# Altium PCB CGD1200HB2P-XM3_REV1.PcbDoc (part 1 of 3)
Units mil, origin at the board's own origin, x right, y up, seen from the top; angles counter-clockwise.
Board outline 2086.61 x 3149.61 mil, 6 copper layers (TOP, LAYER2, LAYER3, LAYER4, LAYER5, BOTTOM), stack 57.2 mil thick; 178 components, 101 nets, 513 pads, 419 vias.
Unrouted connection lines stored in the file: 206.
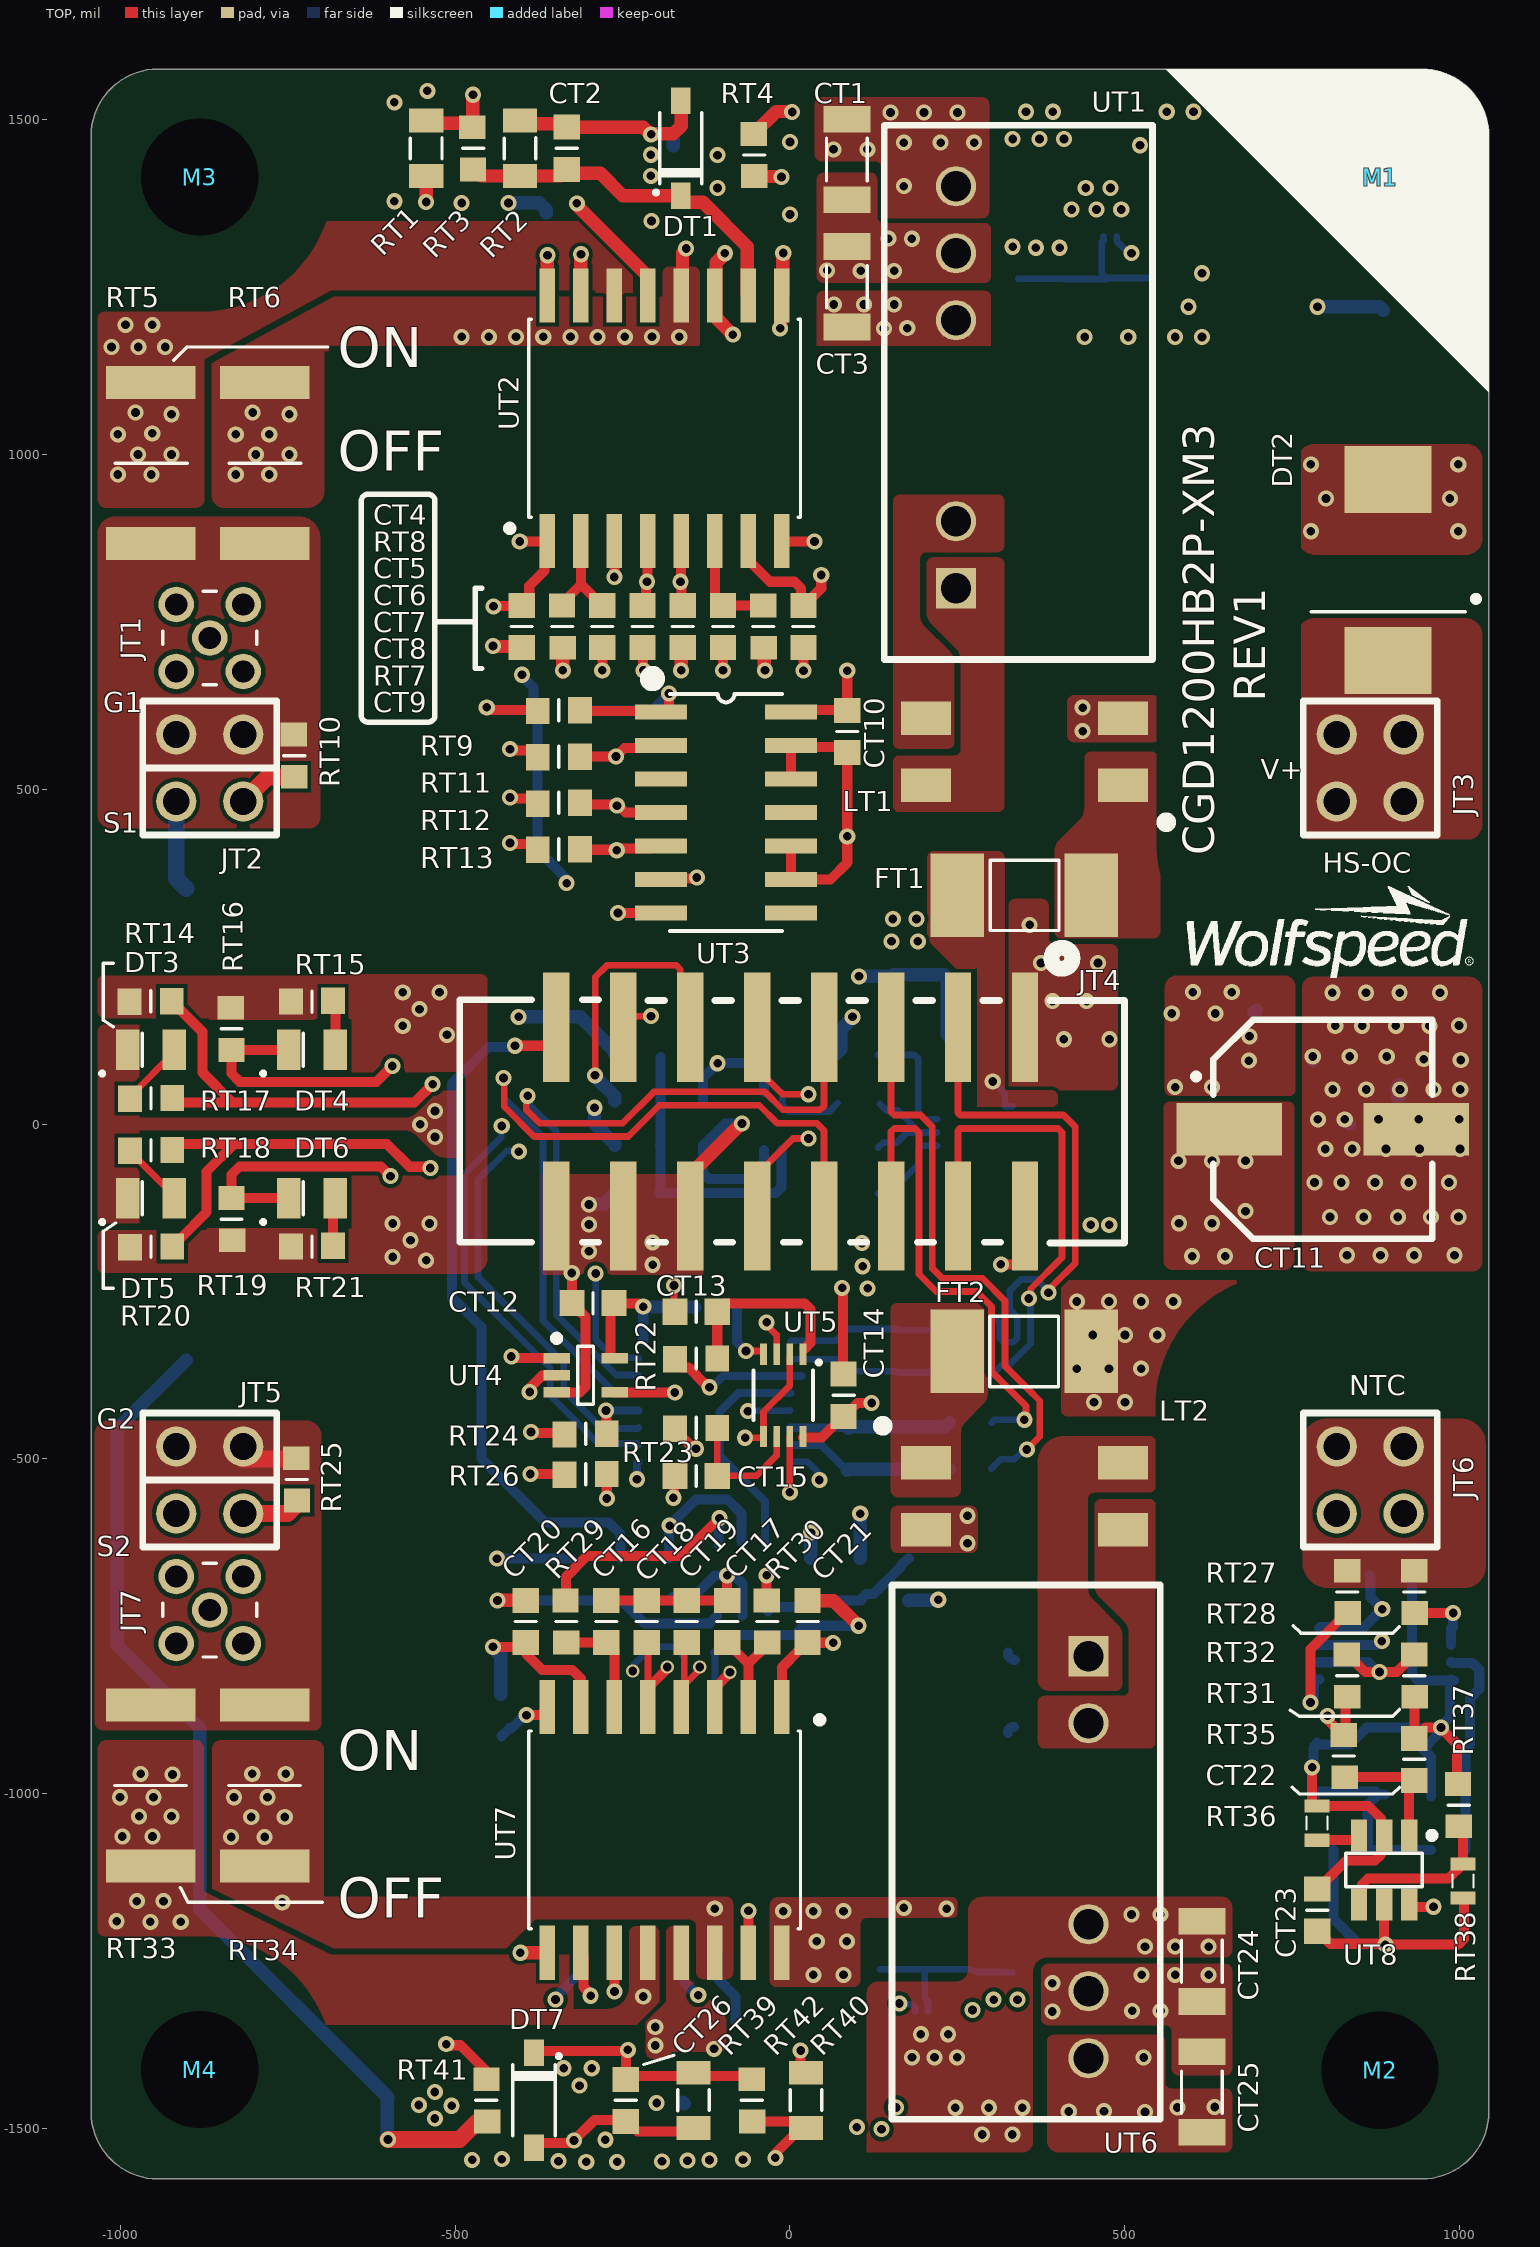
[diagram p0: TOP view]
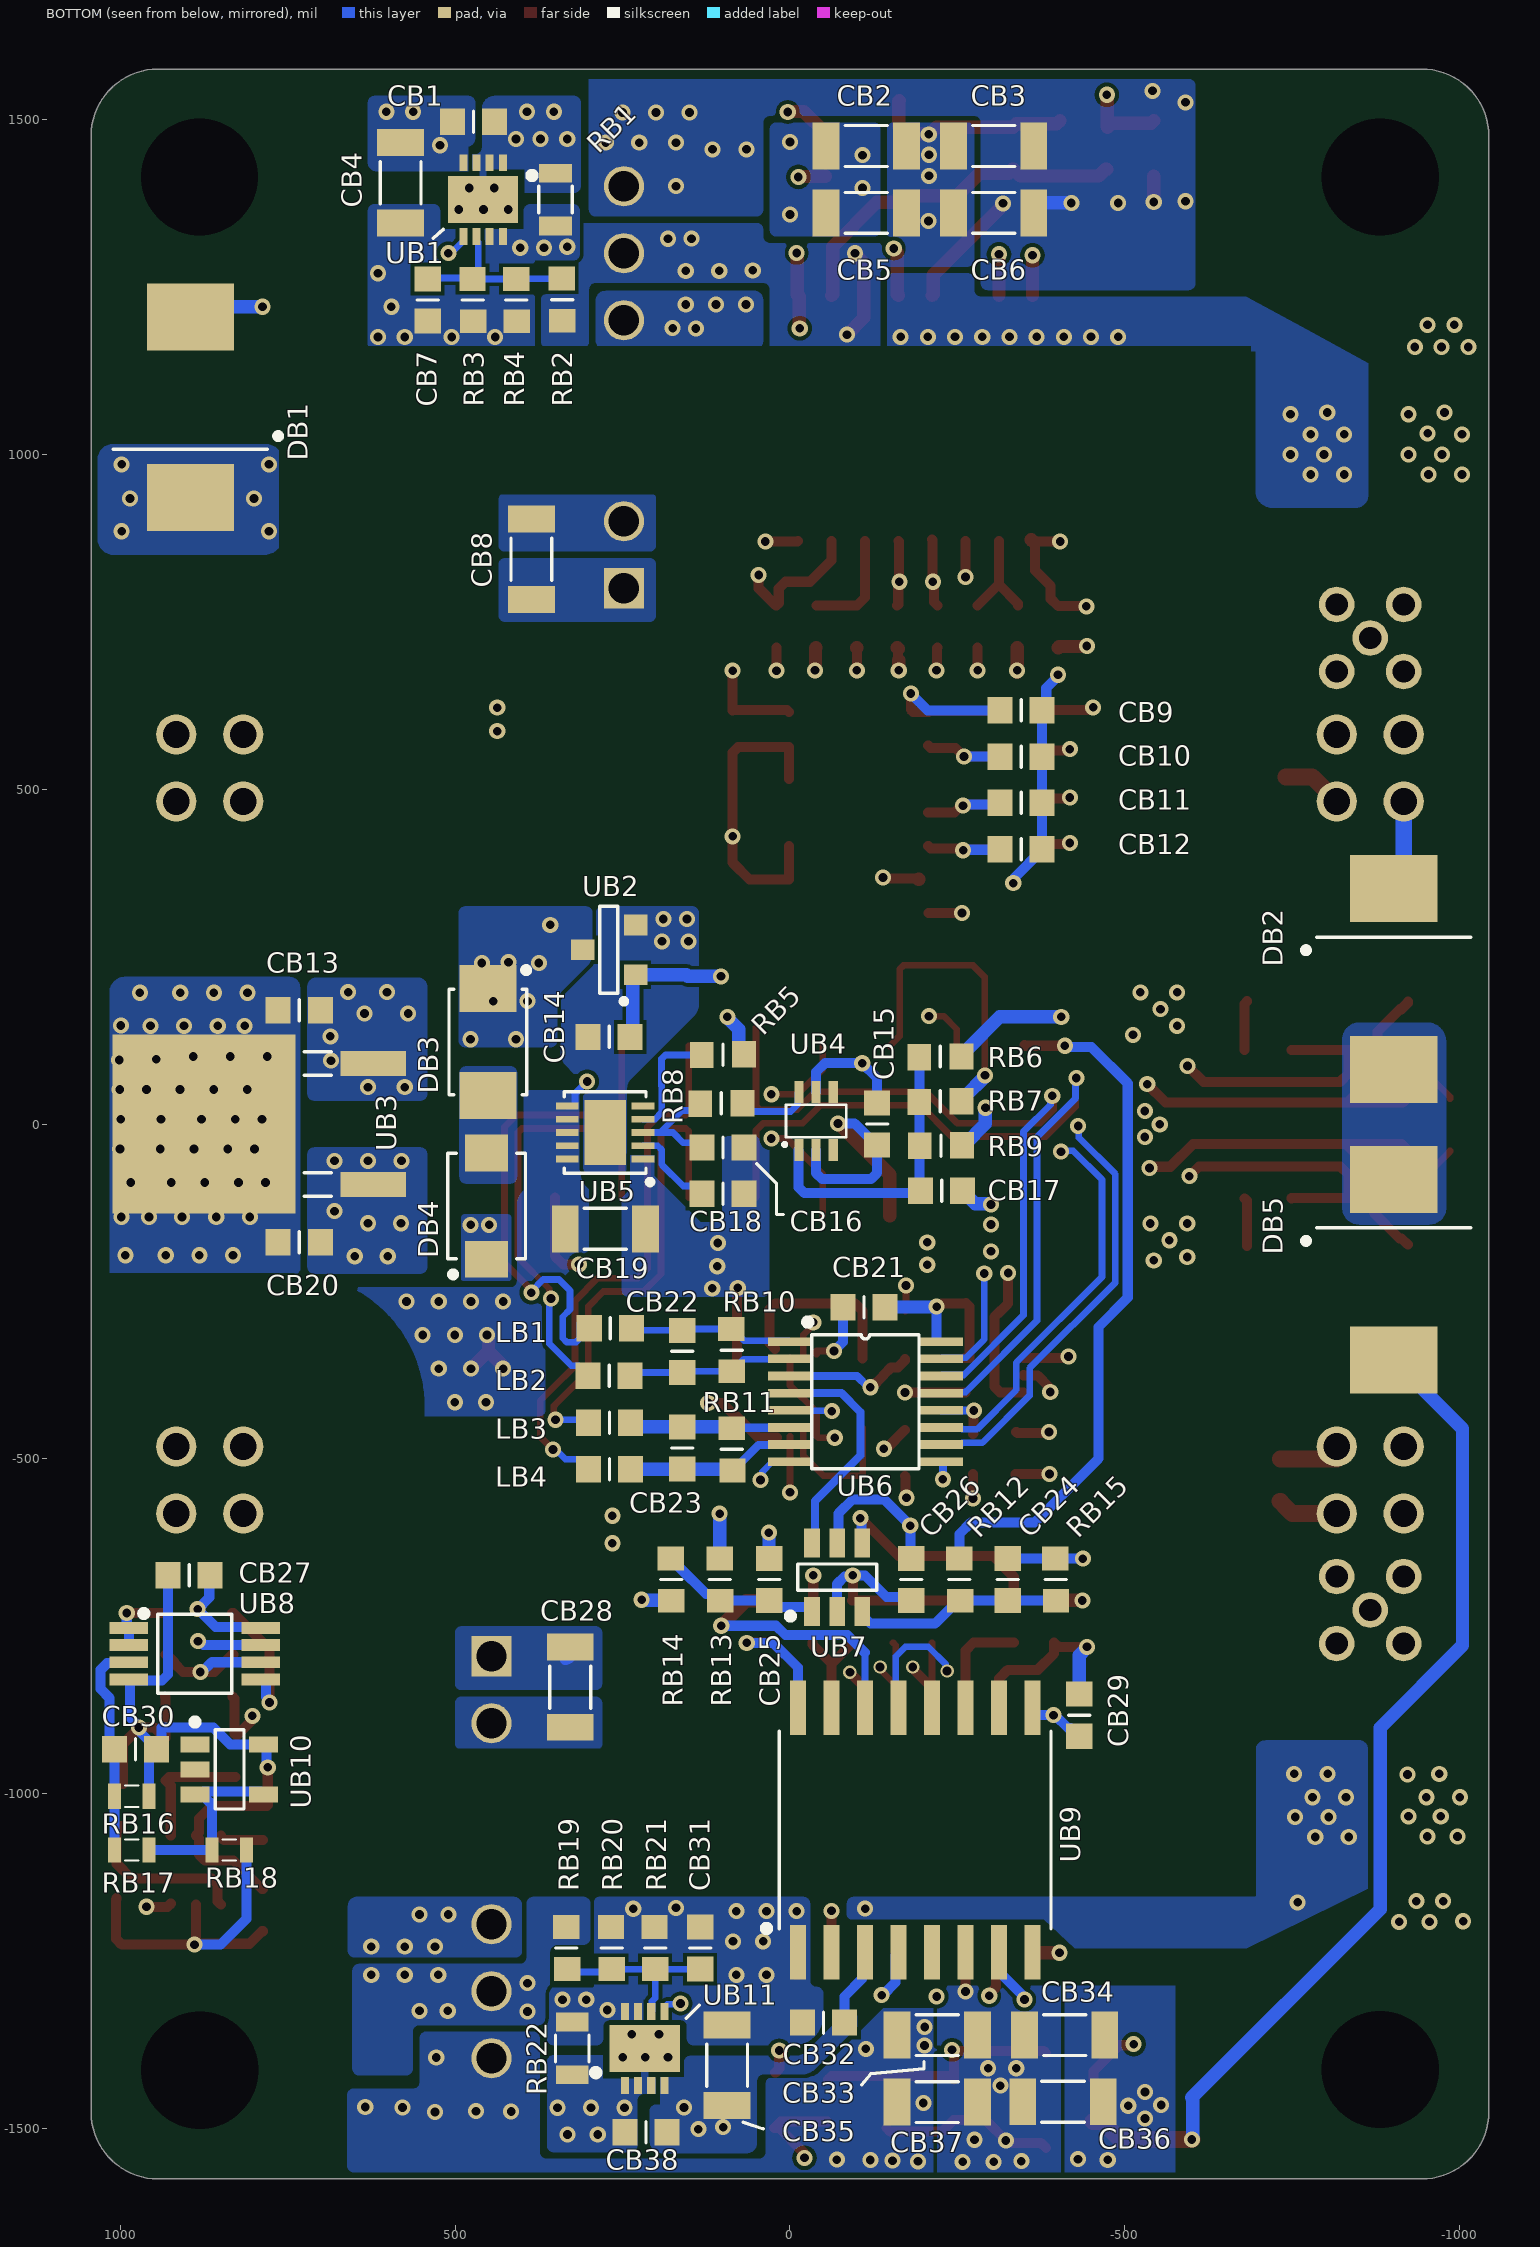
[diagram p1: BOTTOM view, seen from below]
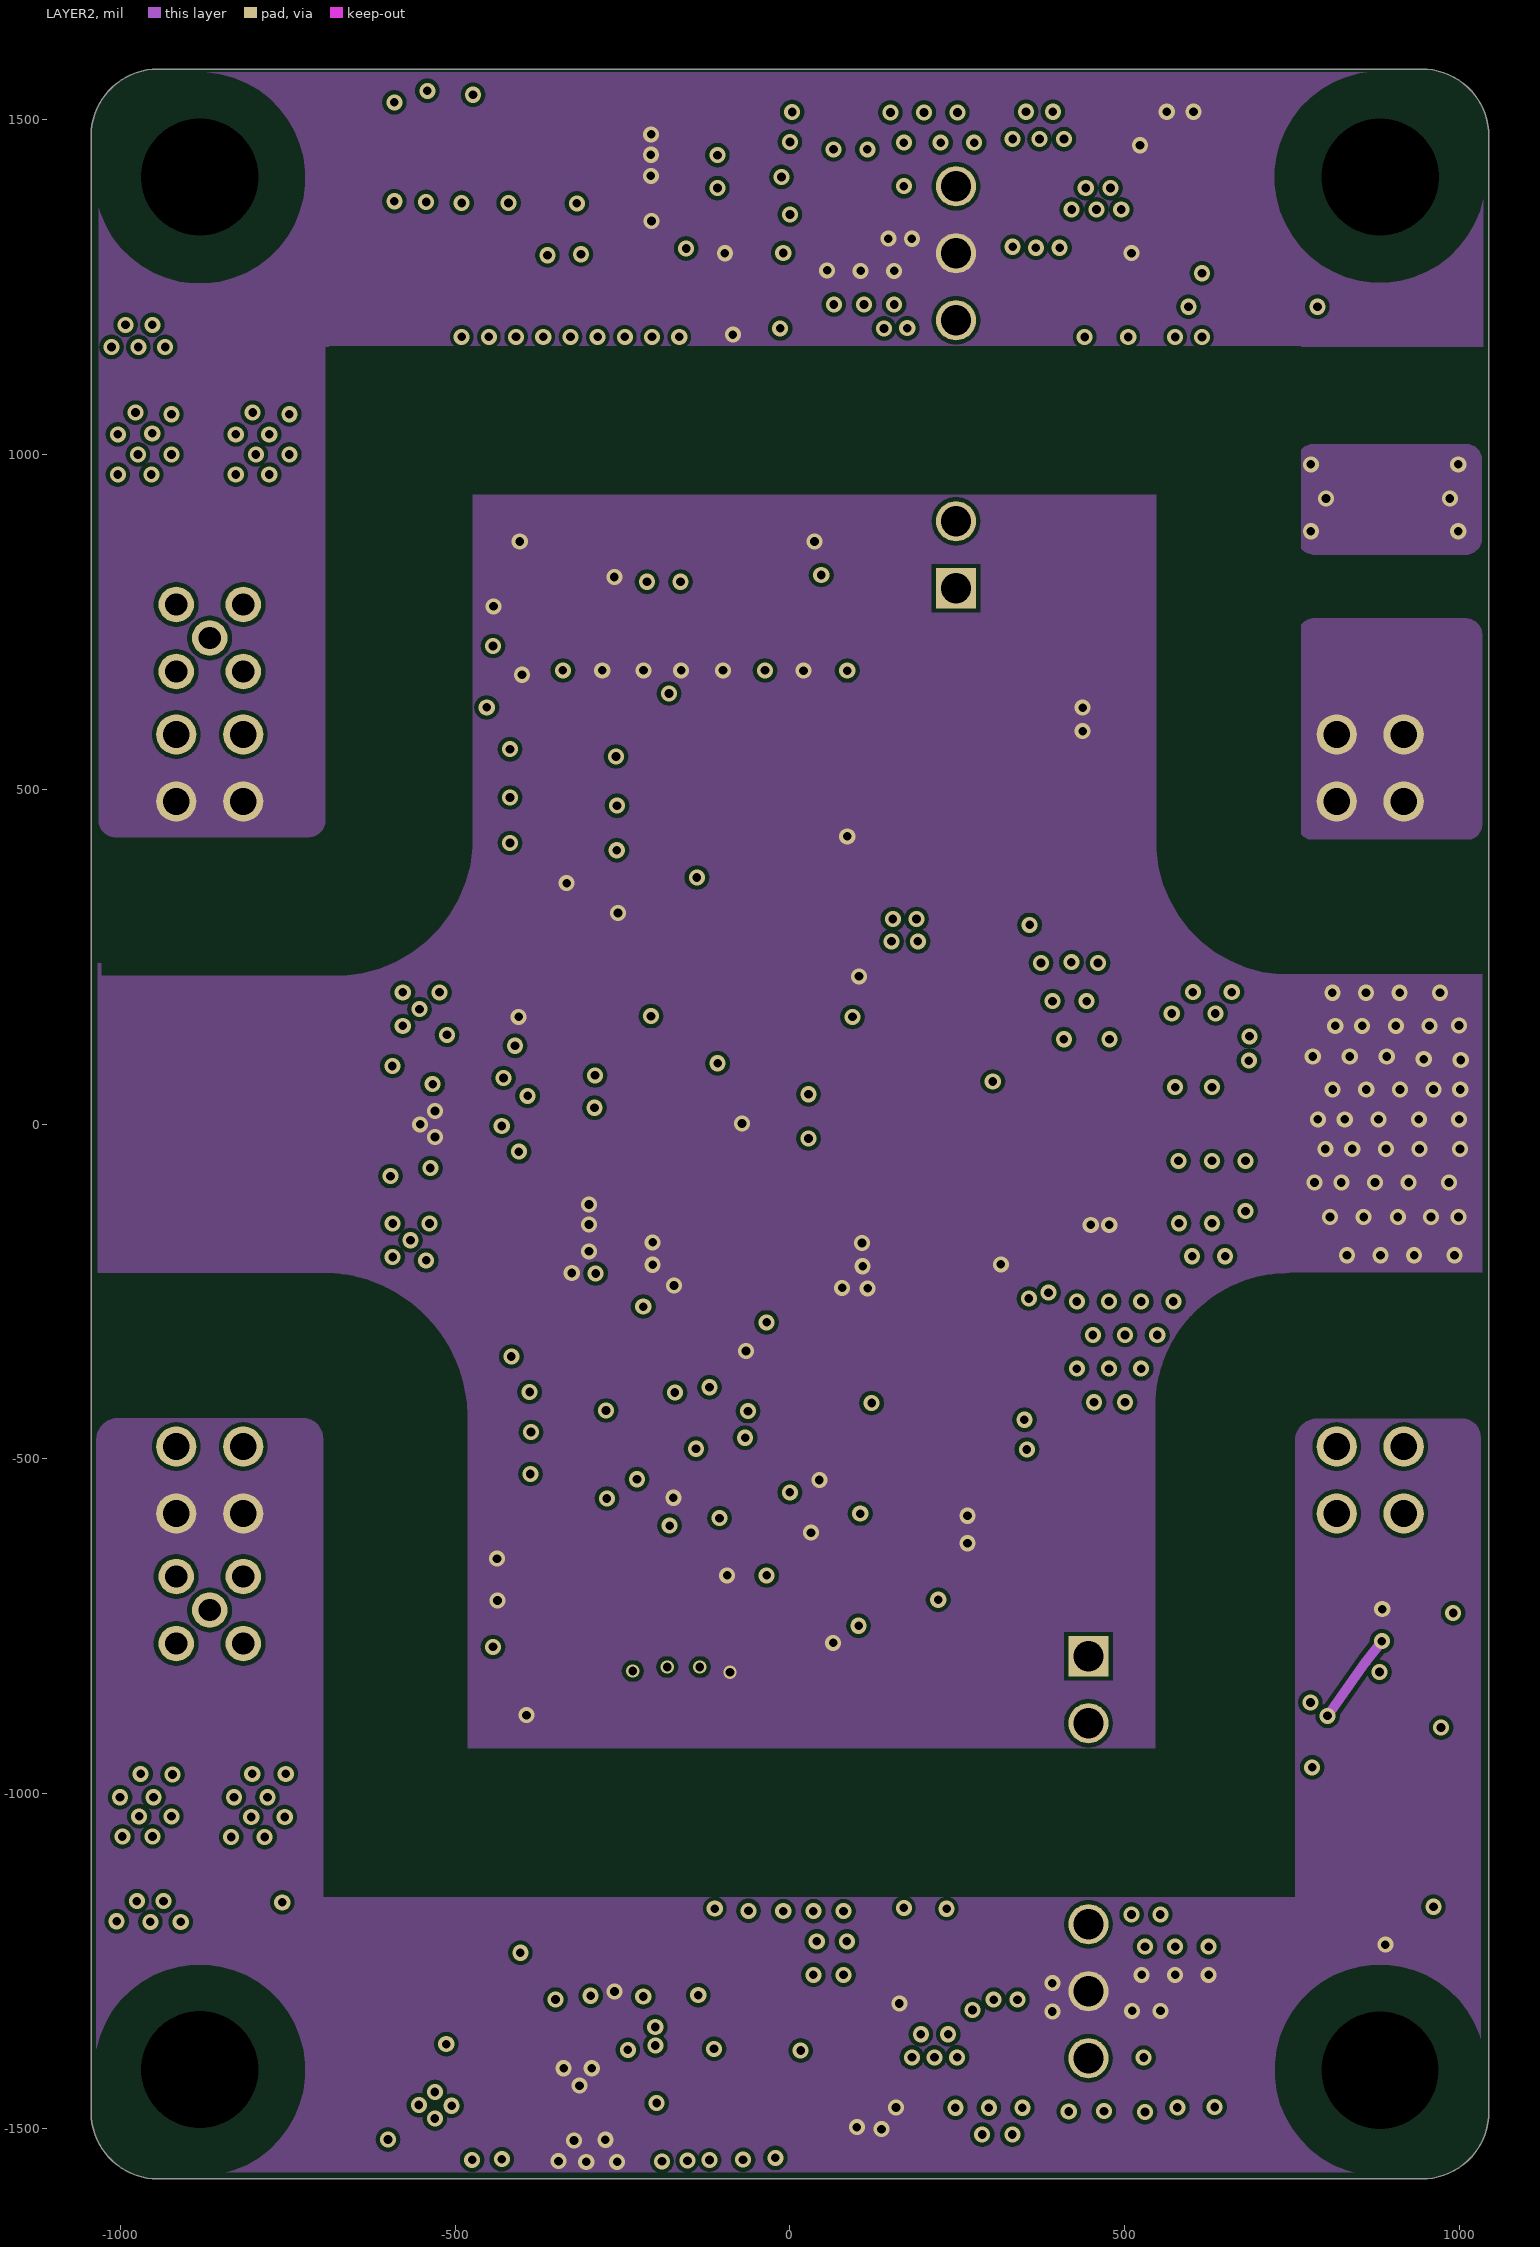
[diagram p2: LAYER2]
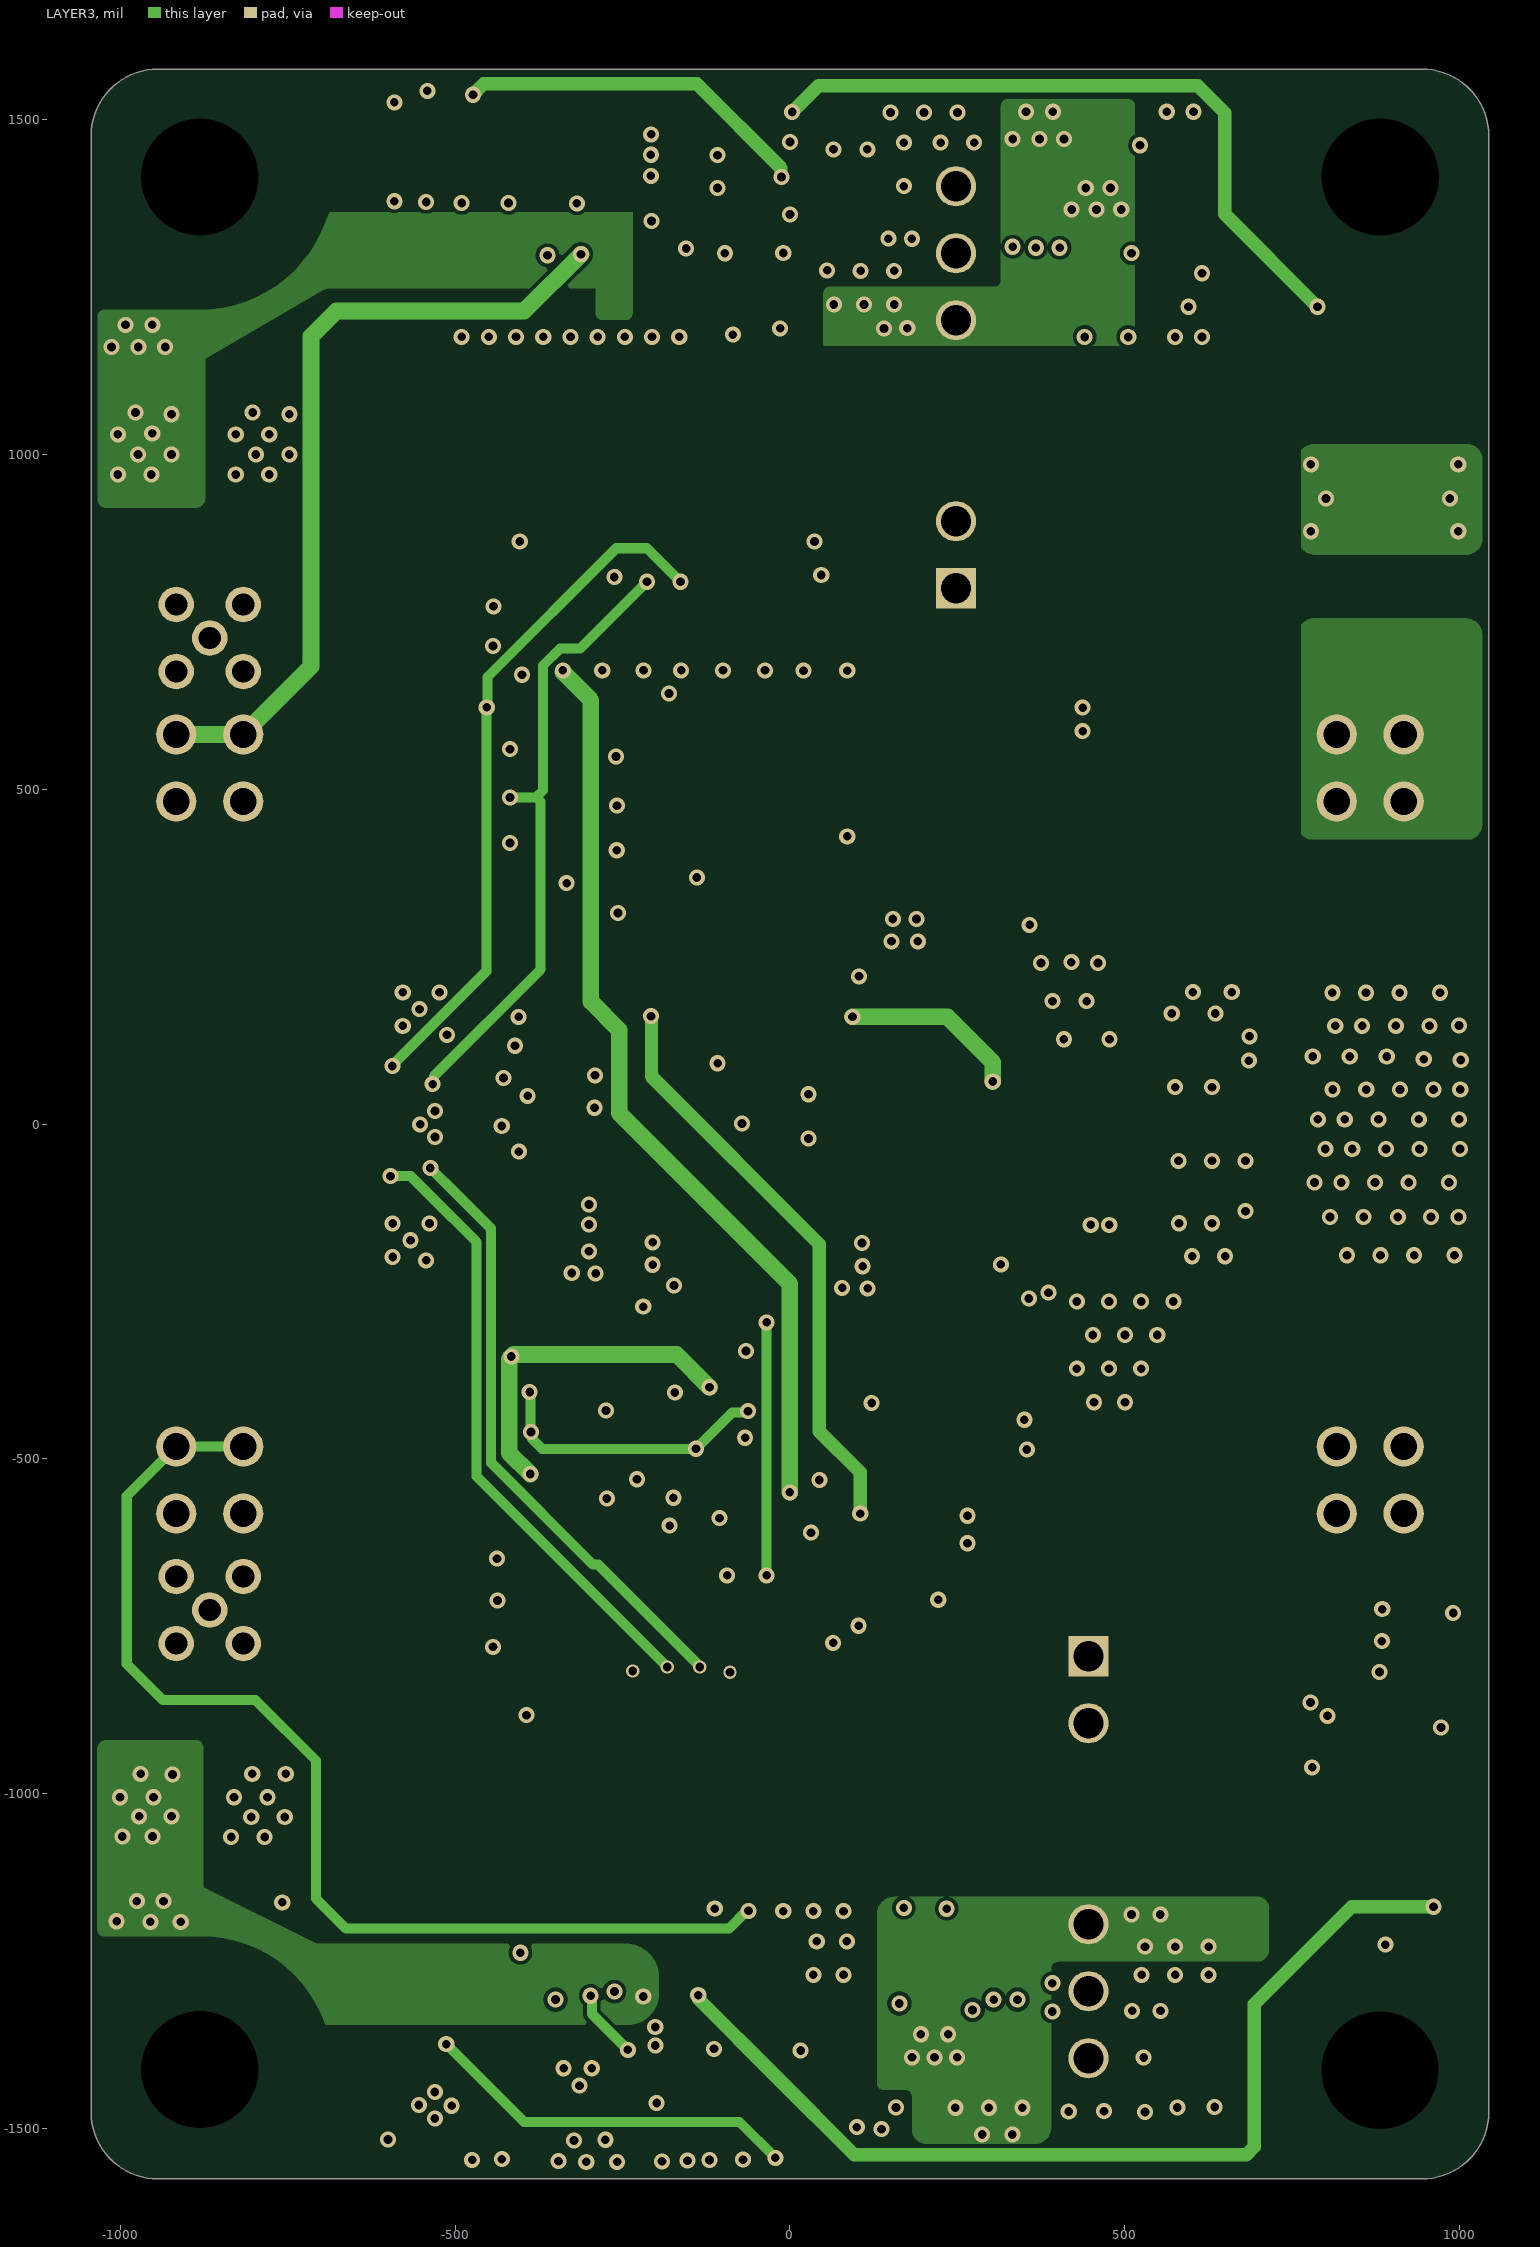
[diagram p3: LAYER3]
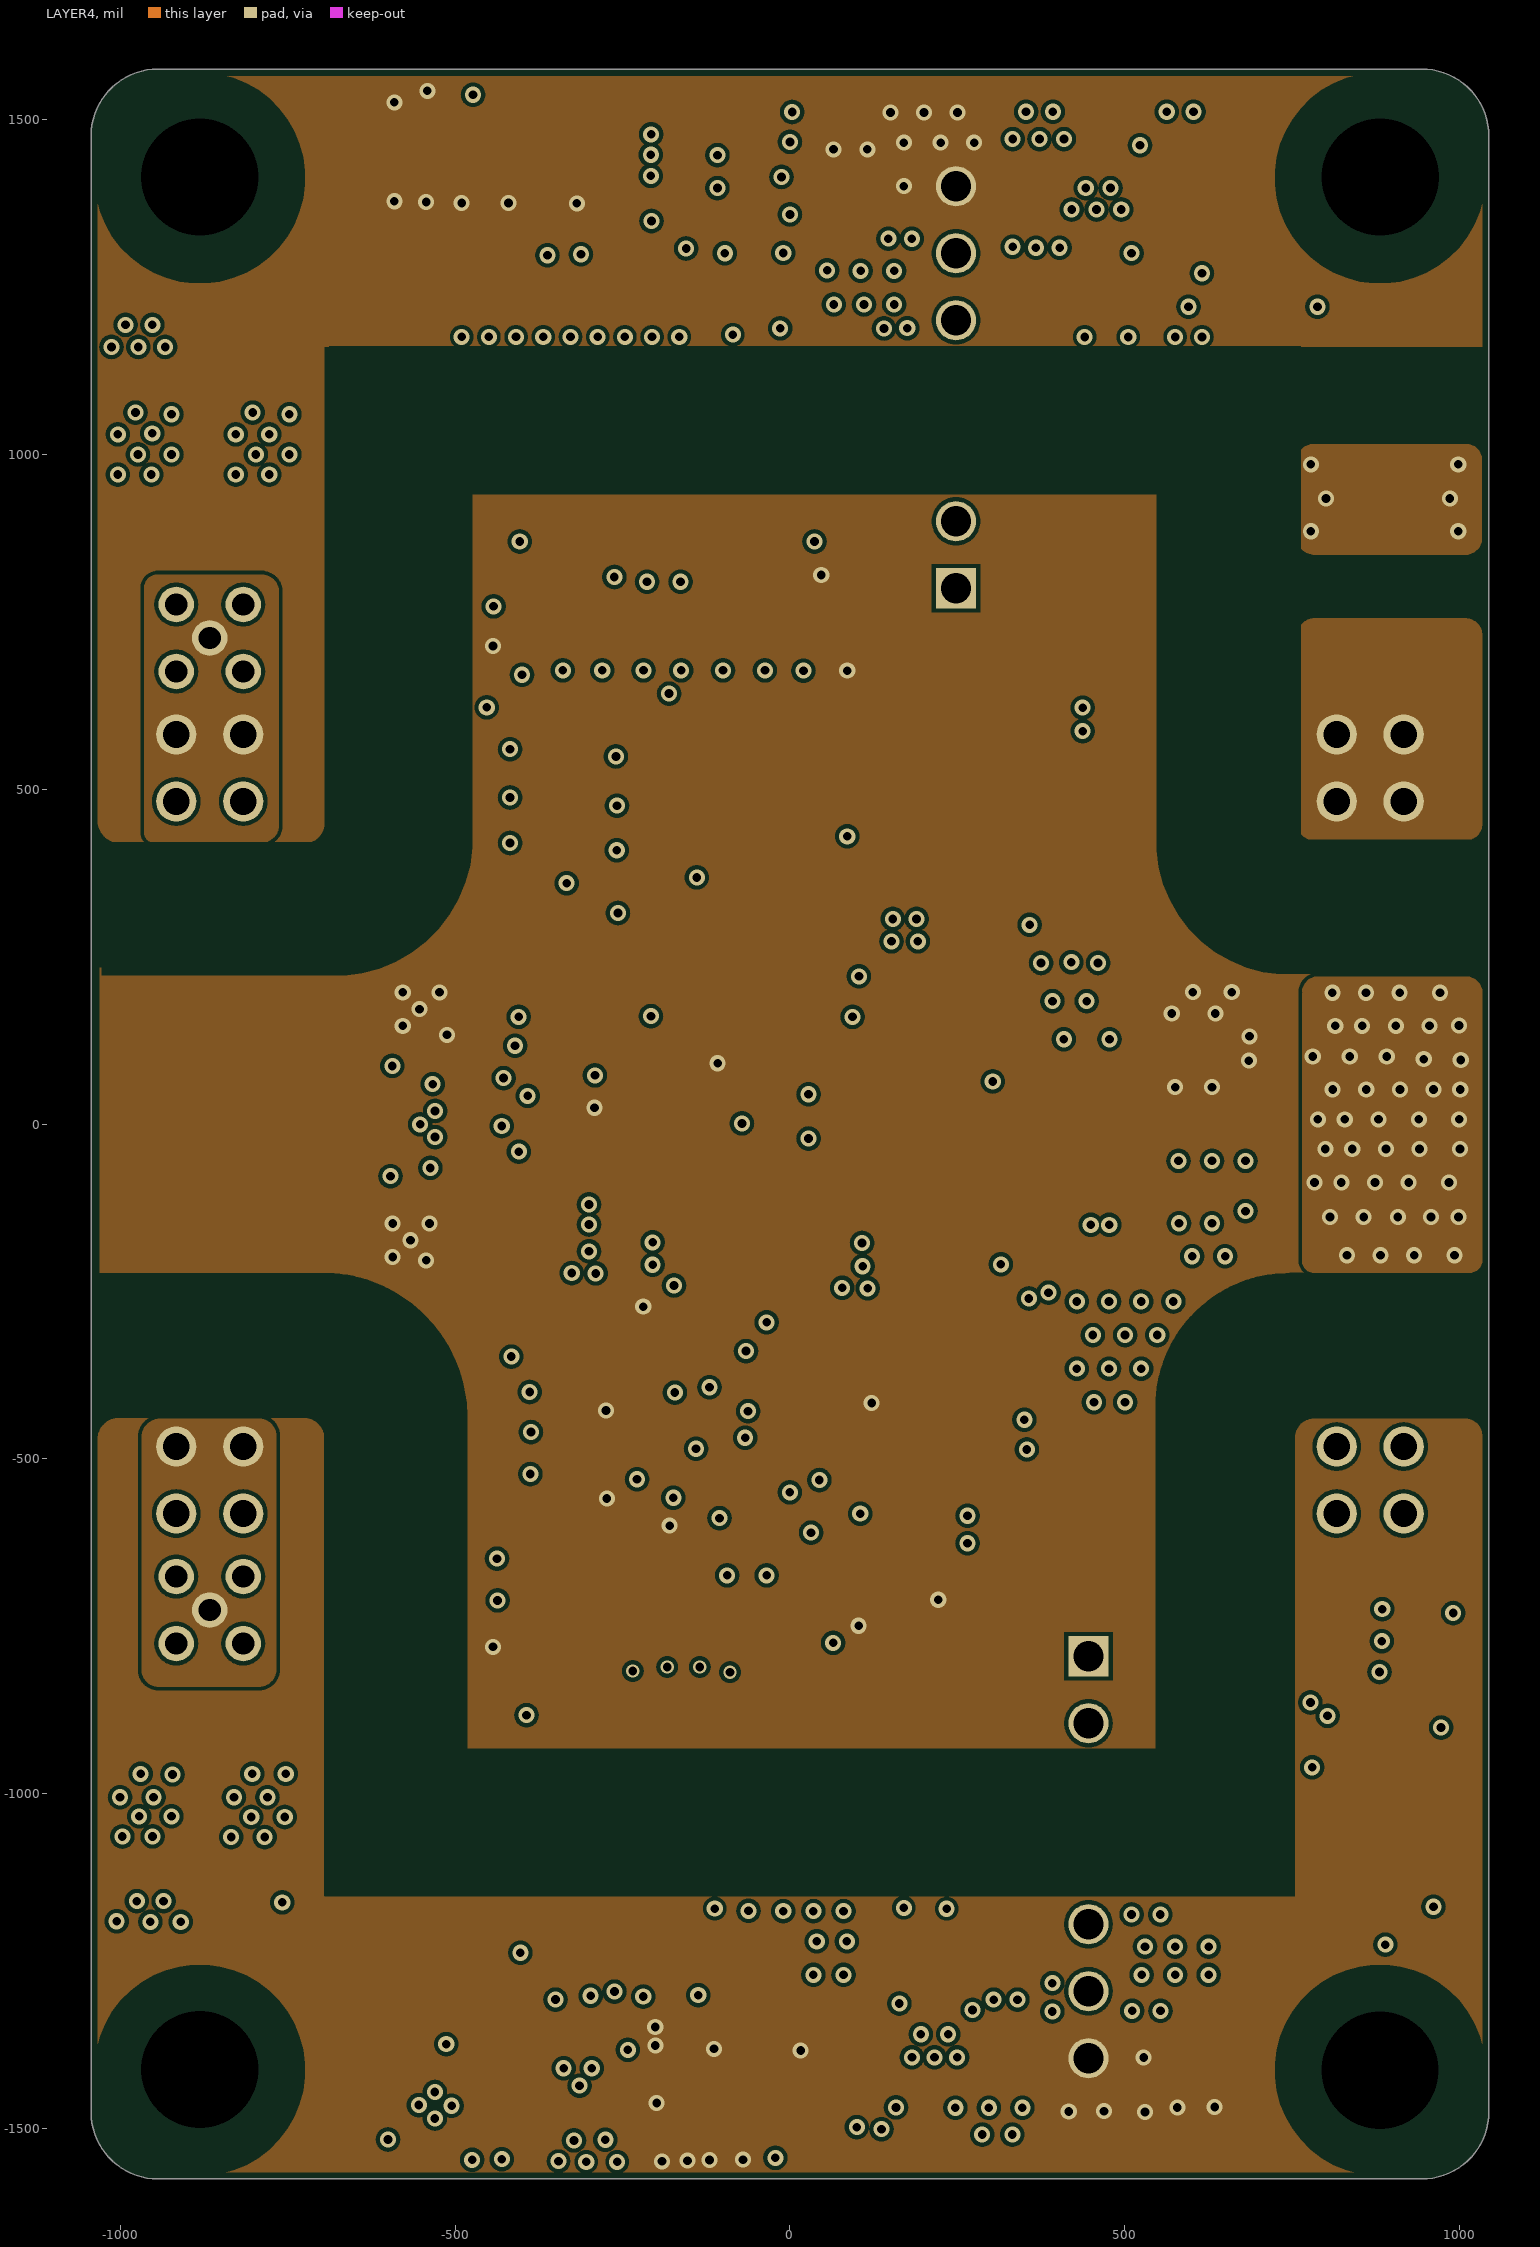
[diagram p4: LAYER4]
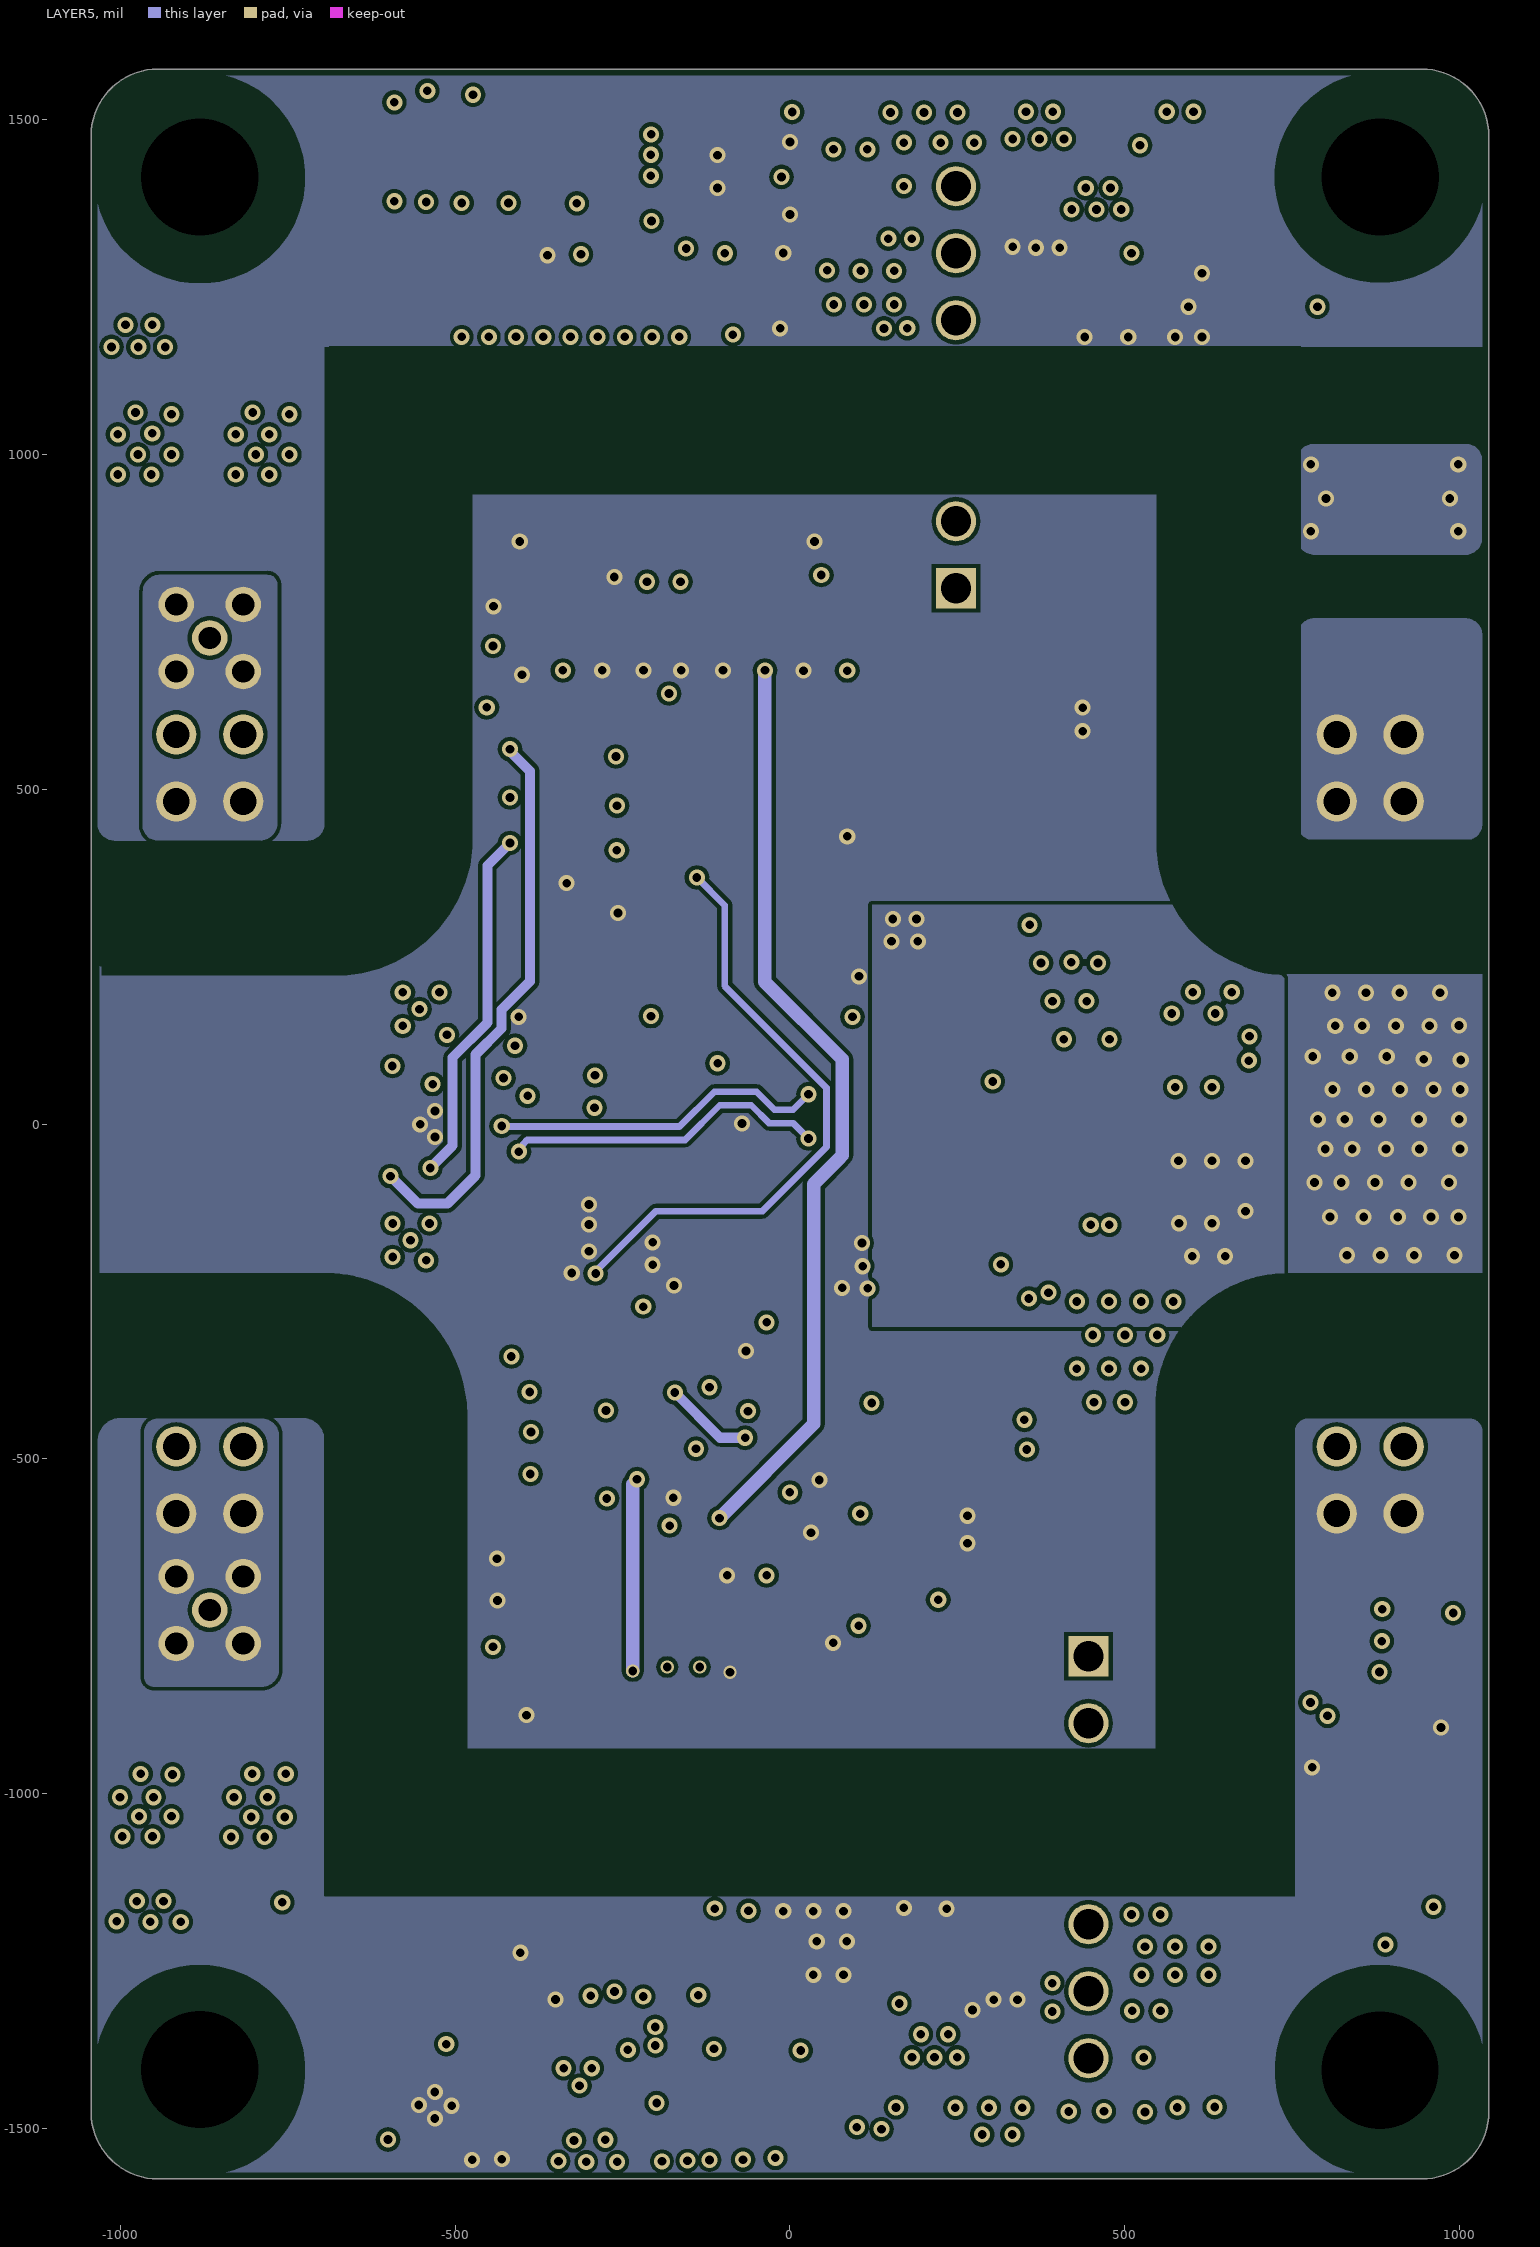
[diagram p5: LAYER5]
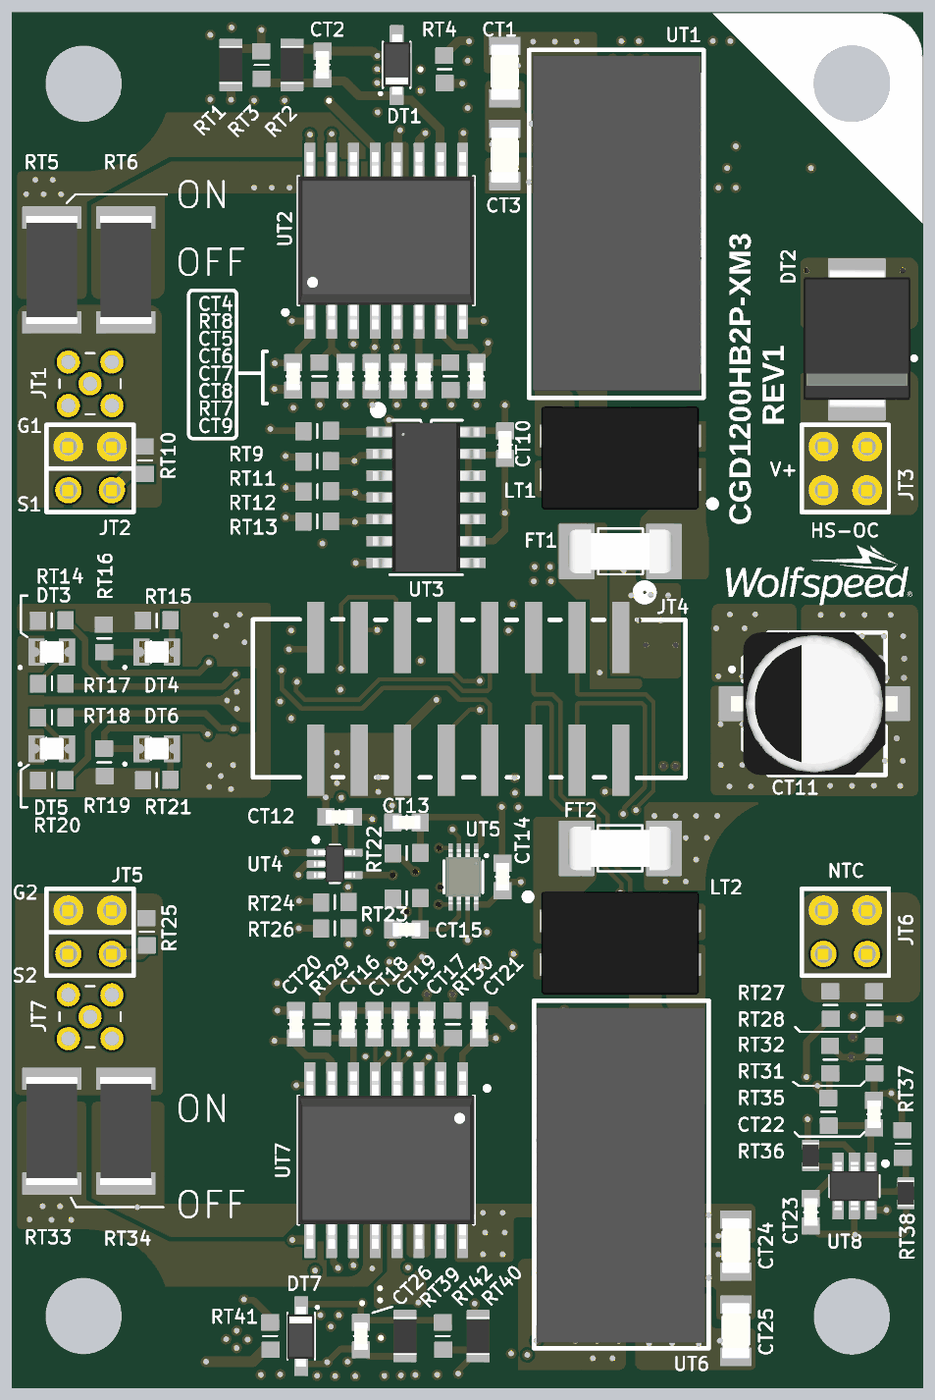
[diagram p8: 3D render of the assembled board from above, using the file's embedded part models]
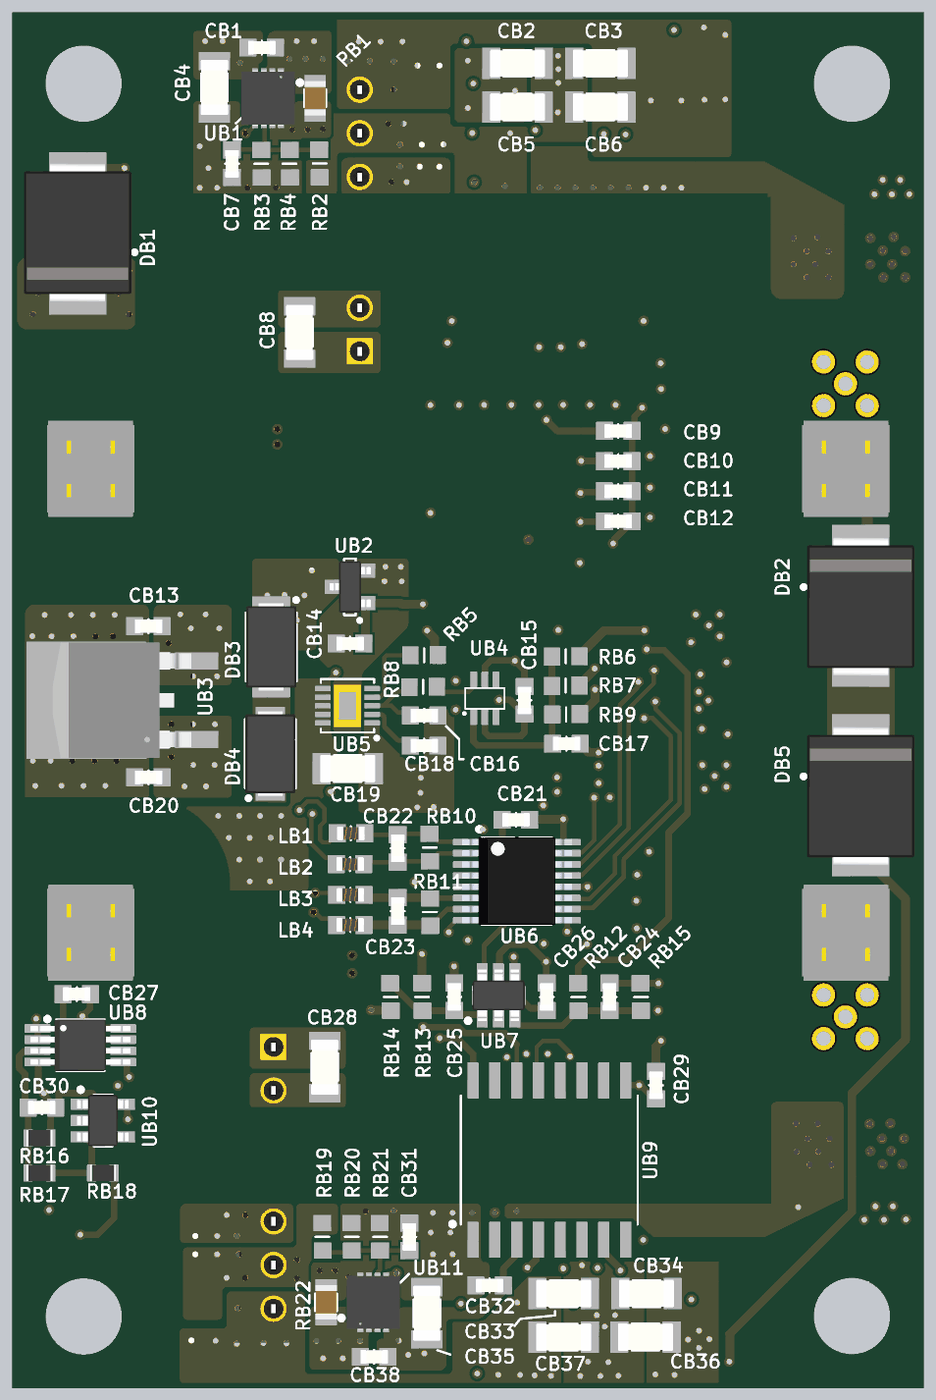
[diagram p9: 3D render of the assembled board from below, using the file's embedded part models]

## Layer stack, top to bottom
Top Solder: solder mask 0.4, Solder Resist, Dk 3.5
TOP: signal copper 1.2
Dielectric 1: core 10, FR-4, Dk 4.5
LAYER2: signal copper 1.2
Dielectric3: core 10, FR-4, Dk 4.5
LAYER3: signal copper 1.2
Dielectric4: core 10, FR-4, Dk 4.5
LAYER4: signal copper 1.2
Dielectric5: core 10, FR-4, Dk 4.5
LAYER5: signal copper 1.2
Dielectric6: core 10, FR-4, Dk 4.5
BOTTOM: signal copper 1.2
Bottom Solder: solder mask 0.4, Solder Resist, Dk 3.5

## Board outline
-1043.31,-1474.8 ccw(c-943.31,-1474.8) -943.31,-1574.8 943.31,-1574.8 ccw(c943.31,-1474.8) 1043.31,-1474.8 1043.31,1474.8 ccw(c943.31,1474.8) 943.31,1574.8 -943.31,1574.8 ccw(c-943.31,1474.8) -1043.31,1474.8

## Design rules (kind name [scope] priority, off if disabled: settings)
Clearance HS850V_Clearance_Rule [InNetClass('HS_850V') vs InNet('HS-DRAIN')] p1: gap=94.49 ignorepadtopadclearanceinfootprint=TRUE
Clearance LS850V_Clearance_Rule [InNetClass('LS_850V') vs InNet('HS-SOURCE')] p2: gap=94.49 ignorepadtopadclearanceinfootprint=TRUE
Clearance HS_To_Any_Outer [(InComponentClass('HS_Components') Or InNetClass('HS_Nets') Or InNet('HS-SOURCE') Or InNet('No Net')) And (OnLayer('Top') or OnLayer('Bottom')) vs (Not InComponentClass('HS_Components') And Not InNetClass('HS_Nets') And Not InNet('HS-SOURCE') And Not InNet('No Net')) And (OnLayer('Top') or OnLayer('Bottom'))] p3: gap=220.47 ignorepadtopadclearanceinfootprint=TRUE // 5.6mm Clearance to any Component not in HS Region
Clearance HS_To_Any_Inner [(InComponentClass('HS_Components') Or InNetClass('HS_Nets') Or InNet('HS-SOURCE') Or InNet('No Net')) And Not (OnLayer('Top') or OnLayer('Bottom')) vs (Not InComponentClass('HS_Components') And Not InNetClass('HS_Nets') And Not InNet('HS-SOURCE') And Not InNet('No Net')) And Not (OnLayer('Top') or OnLayer('Bottom'))] p4: gap=188.98 ignorepadtopadclearanceinfootprint=TRUE // 5.6mm Clearance to any Component not in HS Region
Clearance LS_To_Any_Outer [(InComponentClass('LS_Components') Or (InNetClass('LS_Nets') Or InNetClass('LS_850V')) Or InNet('LS-SOURCE') Or InNet('No Net')) And (OnLayer('Top') or OnLayer('Bottom')) vs (Not InComponentClass('LS_Components') And Not InNetClass('LS_Nets') And Not InNetClass('LS_850V') And Not InNet('LS-SOURCE') And Not InNet('No Net') And Not InNet('Gate Sense HS')) And (OnLayer('Top') or OnLayer('Bottom'))] p5: gap=220.47 ignorepadtopadclearanceinfootprint=TRUE // 5.6mm Clearance to any Component not in HS Region
Clearance LS_To_Any_Inner [(InComponentClass('LS_Components') Or (InNetClass('LS_Nets') Or InNetClass('LS_850V')) Or InNet('LS-SOURCE') Or InNet('No Net')) And Not (OnLayer('Top') or OnLayer('Bottom')) vs (Not InComponentClass('LS_Components') And Not InNetClass('LS_Nets') And Not InNetClass('LS_850V') And Not InNet('LS-SOURCE') And Not InNet('No Net') And Not InNet('Gate Sense HS')) And Not (OnLayer('Top') or OnLayer('Bottom'))] p6: gap=188.98 ignorepadtopadclearanceinfootprint=TRUE // 5.6mm Clearance to any Component not in HS Region
Clearance Default_Clearance_Rule [All] p7: gap=6 ignorepadtopadclearanceinfootprint=TRUE
DiffPairsRouting [All] p1: maxlimit=10 minlimit=10 mostfreqgap=10 toplayer_minwidth=9 toplayer_maxwidth=10 toplayer_prefwidth=10 midlayer1_minwidth=9 midlayer1_maxwidth=10 midlayer1_prefwidth=10 midlayer2_minwidth=9 midlayer2_maxwidth=10 midlayer2_prefwidth=10 midlayer3_minwidth=9 midlayer3_maxwidth=10 midlayer3_prefwidth=10 midlayer4_minwidth=9 midlayer4_maxwidth=10 midlayer4_prefwidth=10 bottomlayer_minwidth=9 bottomlayer_maxwidth=10 bottomlayer_prefwidth=10 maxuncoupledlength=500
HoleSize [All] p1: absolutevalues=TRUE maxlimit=200 minlimit=12 maxpercent=80.000 minpercent=20.000
HoleToHoleClearance [All] p1: gap=0 allowstackedmicrovias=TRUE
MinimumSolderMaskSliver [All] p1: minsoldermaskwidth=0.01
NetAntennae [All] p1: netantennaetolerance=3
PasteMaskExpansion [All] p1: expansion=1
PlaneClearance [All] p1: clearance=0.01
PlaneConnect [All] p1: planeconnectstyle=Direct reliefexpansion=20 reliefentries=4 reliefconductorwidth=10 reliefairgap=10
PolygonConnect [All] p1: connectstyle=Direct reliefconductorwidth=10 reliefentries=4 polygonreliefangle="90 Angle" airgapwidth=10
RoomDefinition HS_Components [InComponentClass('HS_Components')] p1: confinementstyle=ConfineIn formatcopy=TRUE lockcomponents=FALSE outline -1040.35,829.69 -1040.35,1169.24 -978.41,1169.24 -978.41,1534.65 -588.49,1534.65 -588.49,1560.75 -217.87,1560.75 -217.87,1594.49 -108.25,1594.49 -108.25,1565.22 145,1565.22 145,1534.65 978.4,1534.65 978.4,1295.98 1033.5,1295.98 1033.5,1040.33 1049.93,1040.33 1049.93,618 981.14,618 981.14,412.24 -981.15,412.24 -981.15,829.69
RoomDefinition LS_Components [InComponentClass('LS_Components')] p2: confinementstyle=ConfineIn formatcopy=TRUE lockcomponents=FALSE outline -1041.34,-1153.55 -1041.34,-821.5 -1039.81,-821.5 -1039.81,422.98 -751.37,422.98 -751.37,-410.75 981.14,-410.75 981.14,-710.84 1037.3,-710.84 1037.3,-893.97 1048,-893.97 1048,-973.07 1038.52,-973.07 1038.52,-1039.5 1038.52,-1119.5 1037.09,-1119.5 1037.09,-1133.19 1032.93,-1133.19 1032.93,-1229.5 978.4,-1229.5 978.4,-1509.95 670,-1509.95 670,-1545.06 -327.25,-1545.06 -327.25,-1569.42 -436.87,-1569.42 -436.87,-1527.17 -493.2,-1527.17 -493.2,-1514.62 -507.61,-1514.62 -507.61,-1509.95 -978.41,-1509.95 -978.41,-1153.55
RoutingVias [All] p1: holewidth=12.99 width=24.02 viastyle="Through Hole" minholewidth=12.99 minwidth=24.02 maxholewidth=12.99 maxwidth=24.02
SilkToSilkClearance [All] p1: silktosilkclearance=0.01
SilkToSolderMaskClearance [IsPad] p1: minsilkscreentomaskgap=0 clearancetoexposedcopper=TRUE
SolderMaskExpansion SolderMaskExpansion_1 [IsVia] p1: expansion=4 istentingtop=TRUE
SolderMaskExpansion [All] p2: expansion=0 istentingtop=FALSE
UnRoutedNet [All] p1: checkbadconnections=TRUE
Width [All] p1: maxlimit=25 minlimit=8 preferedwidth=20
19 further rules are at their usual default settings.

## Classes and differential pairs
net class LS_Nets: -5V_LS "Gate Sense LS" HS-Source LS-RTD-REF LS-Source LS-VDD LS-Vref LS-VSS NetCB31_2 NetCT22_1 NetCT26_1 NetDB2_A NetDB5_A NetRT27_1 NetRT28_1 NetRT31_2 NetRT32_2 NetRT36_1 NetRT37_2 NetRT40_2 RTD RTD-ISO UB8NC1 UB8NC2 UB8NC3 UB8NC4 VOUT_OFF_LS VOUT_ON_LS
net class LS_850V: NetDB2_A
net class HS_Nets: -5V_HS "Gate Sense HS" HS-Drain HS-Source HS-VDD HS-VSS NetCB7_2 NetCT2_1 NetDB1_A NetDB1_C NetRT1_2 VOUT_OFF_HS VOUT_ON_HS
net class HS_850V: NetDB1_C
component class HS_Components: CB1 CB2 CB3 CB4 CB5 CB6 CB7 CT1 CT2 CT3 DB1 DT1 DT2 JT1 M1 M3 RB1 RB2 RB3 RB4 RT1 RT2 RT3 RT5 RT6 RT10 UB1
component class LS_Components: CB27 CB30 CB31 CB32 CB33 CB34 CB35 CB36 CB37 CB38 CT22 CT23 CT24 CT25 CT26 DB2 DB5 DT7 JT7 M2 M4 RB16 RB18 RB19 RB20 RB21 RB22 RT25 RT27 RT28 RT31 RT32 RT33 RT34 RT35 RT36 RT37 RT38 RT39 RT40 RT42 UB8 UB10 UB11 UT8
differential pair FAULT-Output: +FAULT-Output_P -FAULT-Output_N
differential pair RTD-Output: +RTD-Output_P -RTD-Output_N
differential pair LS-PWM: +LS-PWM_P -LS-PWM_N
differential pair HS-PWM: +HS-PWM_P -HS-PWM_N

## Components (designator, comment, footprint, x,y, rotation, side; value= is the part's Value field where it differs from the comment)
CB1 "2.2uF" CAPC1608X90N 472.44,1496.06 r180 bottom
CB2 "10uF" C_1206 -114.01,1459.94 r0 bottom
CB3 "10uF" C_1206 -304.01,1459.94 r0 bottom
CB4 "10uF" C_1206 581.19,1404.94 r90 bottom
CB5 "10uF" C_1206 -114.01,1359.94 r0 bottom
CB6 "10uF" C_1206 -304.01,1359.94 r0 bottom
CB7 "10000pF" CAPC1608X90N 540.86,1229.94 r90 bottom
CB8 "10uF" C_1206 386,842.95 r90 bottom
CB9 "56 pF" CAPC1608X90N -345.06,617.41 r180 bottom
CB10 "56 pF" CAPC1608X90N -345.06,548.36 r180 bottom
CB11 "56 pF" CAPC1608X90N -345.06,479.3 r180 bottom
CB12 "56 pF" CAPC1608X90N -345.06,410.25 r180 bottom
CB13 "2.2uF" CAPC1608X90N 732.49,169.82 r180 bottom
CB14 "2.2uF" CAPC1608X90N 269.99,129.94 r0 bottom
CB15 "2.2uF" CAPC1608X90N -130,-0.05 r270 bottom
CB16 "56 pF" CAPC1608X90N 99.99,-35.06 r180 bottom
CB17 "10000pF" CAPC1608X90N -226.38,-99.41 r180 bottom
CB18 "56 pF" CAPC1608X90N 99.99,-104.11 r180 bottom
CB19 "10uF" C_1206 275.45,-156.46 r180 bottom
CB20 "2.2uF" CAPC1608X90N 732.49,-176.64 r180 bottom
CB21 "2.2uF" CAPC1608X90N -110.62,-273.8 r0 bottom
CB22 "56 pF" CAPC1608X90N 160.83,-339.46 r90 bottom
CB23 "56 pF" CAPC1608X90N 160.83,-483.64 r270 bottom
CB24 "56 pF" CAPC1608X90N -325.04,-680.06 r90 bottom
CB25 "10000pF" CAPC1608X90N 30.94,-680.06 r90 bottom
CB26 "2.2uF" CAPC1608X90N -180.93,-680.06 r270 bottom
CB27 "2.2uF" CAPC1608X90N 896.94,-673.52 r0 bottom
CB28 "10uF" C_1206 328,-840.55 r270 bottom
CB29 "2.2uF" CAPC1608X90N -431.59,-882.45 r90 bottom
CB30 "2.2uF" CAPC1608X90N 976.94,-933.52 r0 bottom
CB31 "10000pF" CAPC1608X90N 134.13,-1230.06 r270 bottom
CB32 "2.2uF" CAPC1608X90N -50.01,-1341.33 r180 bottom
CB33 "10uF" C_1206 -220.01,-1360.06 r180 bottom
CB34 "10uF" C_1206 -410.01,-1360.06 r180 bottom
CB35 "10uF" C_1206 93.79,-1405.06 r270 bottom
CB36 "10uF" C_1206 -407.6,-1459.62 r180 bottom
CB37 "10uF" C_1206 -220.01,-1460.06 r180 bottom
CB38 "2.2uF" CAPC1608X90N 214.99,-1505.06 r0 bottom
CT1 "10uF" C_1206 85,1439.75 r270 top
CT2 "56 pF" CAPC1608X90N -333.06,1456.48 r90 top
CT3 "10uF" C_1206 85,1249.95 r270 top
CT4 "2.2uF" CAPC1608X90N -400.24,742.55 r90 top
CT5 "56 pF" CAPC1608X90N -280.13,742.55 r270 top
CT6 "56 pF" CAPC1608X90N -220.08,742.55 r270 top
CT7 "56 pF" CAPC1608X90N -160.02,742.55 r270 top
CT8 "56 pF" CAPC1608X90N -99.97,742.55 r270 top
CT9 "2.2uF" CAPC1608X90N 20.14,742.55 r270 top
CT10 "2.2uF" CAPC1608X90N 85.52,585.92 r270 top
CT11 "100uF" CAP_EEE1HA101UP 795.28,-7.87 r0 top
CT12 "2.2uF" CAPC1608X90N -294,-267.25 r180 top
CT13 "56 pF" CAPC1608X90N -140.01,-280.06 r180 top
CT14 "2.2uF" CAPC1608X90N 79.99,-404.98 r90 top
CT15 "56 pF" CAPC1608X90N -140.01,-525.43 r180 top
CT16 "56 pF" CAPC1608X90N -274.04,-742.66 r90 top
CT17 "56 pF" CAPC1608X90N -93.88,-742.66 r90 top
CT18 "56 pF" CAPC1608X90N -213.99,-742.66 r90 top
CT19 "56 pF" CAPC1608X90N -153.93,-742.66 r90 top
CT20 "2.2uF" CAPC1608X90N -394.15,-742.66 r90 top
CT21 "2.2uF" CAPC1608X90N 26.23,-742.66 r270 top
CT22 "1UF" CAPC1608X90N 931.94,-948.52 r90 top
CT23 "2.2uF" CAPC1608X90N 786.94,-1173.52 r90 top
CT24 "10uF" C_1206 614.99,-1250.06 r90 top
CT25 "10uF" C_1206 614.99,-1445.06 r90 top
CT26 "56 pF" CAPC1608X90N -245.06,-1457.53 r270 top
DB1 "US3M-13" DO-214AB-SMC 895,1069.95 r90 bottom
DB2 "US3M-13" DO-214AB-SMC -901.31,216.48 r270 bottom
DB3 "SMAJ5932B-TP" DIOM4426X24N_DB3 450.94,122.48 r270 bottom
DB4 "STPS2150A" DIOM4326X26N_DB4 452.94,-122.52 r90 bottom
DB5 "US3M-13" DO-214AB-SMC -901.31,-217.52 r270 bottom
DT1 "BAT42W-TP" SOD123 -163.06,1456.48 r90 top
DT2 "US3M-13" DO-214AB-SMC 893,826.95 r90 top
DT3 "LG R971-KN-1" D_0805 -953.78,110.78 r180 top
DT4 "LH R974-LP-1" D_0805 -713.5,110.78 r180 top
DT5 "LG R971-KN-1" D_0805 -953.78,-110.9 r180 top
DT6 "LH R974-LP-1" D_0805 -713.5,-110.9 r180 top
DT7 "BAT42W-TP" SOD123 -382.06,-1457.53 r270 top
FT1 "750 mA" FUSE_SMD_SSQ2410 349.99,341.34 r0 top
FT2 "750 mA" FUSE_SMD_SSQ2410 349.99,-339.36 r180 top
JT1 "MMCX-J-P-H-ST-TH1" MMCX-J-P-H-ST-TH1_PCB -866.15,725.48 r0 top
JT2 "ESQ-102-33-L-D" CON_2X2_100MIL_TH -866.15,531.45 r0 top
JT3 "ESQ-102-33-L-D" "CON_2x2_100mil_TH - NEW" 866.14,531.45 r0 top
JT4 "CON 2x8 SM" CONN16_3020-16-0300-00_CNC 0.94,3.38 r180 top
JT5 "ESQ-102-33-L-D" CON_2X2_100MIL_TH -866.15,-531.54 r0 top
JT6 "ESQ-102-33-L-D" "CON_2x2_100mil_TH - NEW" 866.14,-531.54 r0 top
JT7 "MMCX-J-P-H-ST-TH1" MMCX-J-P-H-ST-TH1_PCB -866.15,-725.56 r0 top
LB1 "1 uH" INDC1608X95N 268.14,-304.92 r180 bottom
LB2 "1 uH" INDC1608X95N 269.99,-375.55 r180 bottom
LB3 "1 uH" INDC1608X95N 269.38,-446.08 r180 bottom
LB4 "1 uH" INDC1608X95N 269.38,-515.13 r180 bottom
LT1 "10uH" SRF0905 349.99,555.75 r180 top
LT2 "10uH" SRF0905 349.99,-555.86 r0 top
M1 "Mounting_Hole_4.445mm" MOUNTING_HOLE 881.3,1413.48 r0 top
M2 "Mounting_Hole_4.445mm" MOUNTING_HOLE 880.94,-1412.52 r0 top
M3 "Mounting_Hole_4.445mm" MOUNTING_HOLE -881.06,1413.48 r0 top
M4 "Mounting_Hole_4.445mm" MOUNTING_HOLE -881.06,-1411.52 r0 top
RB1 "0" RES_2012_SAM 349.99,1379.94 r270 bottom
RB2 "2.2K" RESC1608X55N 339.69,1230.48 r270 bottom
RB3 "10k" RESC1608X55N 473.83,1229.94 r90 bottom
RB4 "10k" RESC1608X55N 408.83,1229.94 r90 bottom
RB5 "120" RESC1608X55N 99.99,103.05 r0 bottom
RB6 "10k" RESC1608X55N -224.55,100.79 r180 bottom
RB7 "120" RESC1608X55N -224.55,33.82 r180 bottom
RB8 "120" RESC1608X55N 102.49,31.01 r180 bottom
RB9 "10k" RESC1608X55N -225.39,-32.48 r0 bottom
RB10 "120" RESC1608X55N 86.78,-337.5 r270 bottom
RB11 "120" RESC1608X55N 86.78,-485.61 r90 bottom
RB12 "120" RESC1608X55N -252.99,-680.06 r90 bottom
RB13 "120" RESC1608X55N 104.99,-680.06 r90 bottom
RB14 "10k" RESC1608X55N 177.02,-680.06 r270 bottom
RB15 "10k" RESC1608X55N -397.1,-680.06 r270 bottom
RB16 "249k" RESC1608X06N 982.54,-1003.52 r180 bottom
RB17 "100K" RESC1608X06N 982.53,-1083.52 r0 bottom
RB18 "4.99K" RESC1608X06N 836.94,-1083.52 r0 bottom
RB19 "2.2K" RESC1608X55N 333.69,-1230.04 r90 bottom
RB20 "10k" RESC1608X55N 266.16,-1230.06 r270 bottom
RB21 "10k" RESC1608X55N 201.16,-1230.06 r270 bottom
RB22 "0" RES_2012_SAM 324.99,-1380.06 r90 bottom
RT1 "510" RESC2012X06N_510_698 -543.06,1456.48 r90 top
RT2 "887" RESC2012X06N_510_698 -403.06,1456.48 r90 top
RT3 "1K" RESC1608X55N -473.06,1456.48 r270 top
RT4 "330" RESC1608X55N -53.06,1446.48 r270 top
RT5 "1_OHM" RESC6432X70N -954.06,986.49 r270 top
RT6 "1_OHM" RESC6432X70N -784.06,986.48 r270 top
RT7 "120" RESC1608X55N -39.91,742.55 r90 top
RT8 "120" RESC1608X55N -340.19,742.55 r90 top
RT9 "120" RESC1608X55N -345.06,617.42 r0 top
RT10 "10k" RESC1608X55N -740,549.95 r270 top
RT11 "120" RESC1608X55N -345.06,548.36 r0 top
RT12 "120" RESC1608X55N -345.06,479.3 r0 top
RT13 "120" RESC1608X55N -345.06,410.25 r0 top
RT14 "120" RESC1608X55N -954.31,183.48 r0 top
RT15 "330" RESC1608X55N -713.5,182.81 r180 top
RT16 "10k" RESC1608X55N -833.64,142.02 r270 top
RT17 "330" RESC1608X55N -953.78,38.76 r0 top
RT18 "330" RESC1608X55N -953.78,-38.87 r0 top
RT19 "10k" RESC1608X55N -833.64,-142.13 r90 top
RT20 "120" RESC1608X55N -953.78,-182.93 r0 top
RT21 "330" RESC1608X55N -713.5,-182.93 r180 top
RT22 "120" RESC1608X55N -140.01,-350.06 r0 top
RT23 "120" RESC1608X55N -140.01,-453.74 r0 top
RT24 "10k" RESC1608X55N -305.01,-462.56 r0 top
RT25 "10k" RESC1608X55N -735.93,-530.61 r270 top
RT26 "10k" RESC1608X55N -305.01,-522.56 r0 top
RT27 "10k" RESC1608X55N 831.94,-698.52 r90 top
RT28 "330" RESC1608X55N 931.94,-698.52 r90 top
RT29 "120" RESC1608X55N -334.1,-742.66 r270 top
RT30 "120" RESC1608X55N -33.82,-742.66 r270 top
RT31 "10k" RESC1608X55N 931.94,-823.52 r90 top
RT32 "0 OHMS" RESC1608X55N 831.94,-823.52 r270 top
RT33 "1_OHM" RESC6432X70N -954.06,-987.53 r90 top
RT34 "1_OHM" RESC6432X70N -784.06,-987.53 r90 top
RT35 "10k" RESC1608X55N 826.94,-943.52 r90 top
RT36 "249k" RESC1608X06N 786.94,-1043.52 r90 top
RT37 "10k" RESC1608X55N 998.28,-1016.75 r270 top
RT38 "100K" RESC1608X06N 1005,-1130.05 r90 top
RT39 "887" RESC2012X06N_510_698 -144.06,-1457.53 r270 top
RT40 "510" RESC2012X06N_510_698 23.94,-1457.53 r270 top
RT41 "330" RESC1608X55N -453.06,-1457.53 r90 top
RT42 "1K" RESC1608X55N -57.06,-1457.53 r90 top
UB1 "LT3015EDD#TRPBF" 8-WDFN_EXPOSED_PAD 458.09,1379.94 r270 bottom
UB2 "DMP3056L-7" SOT_23_3 269.99,259.94 r270 bottom
UB3 "MC7805BDTG" DPAK-3 874.49,-0.06 r90 bottom
UB4 "SN74LVC2G17DCKR" SOT65P210X110-6N_UB4 -39.06,4.48 r90 bottom
UB5 "MP5000ADQ-LF-P" SON50P300X300X100-11N 275.92,-12.69 r0 bottom
UB6 "2/2" TSSOP_16 -112.58,-414.59 r180 bottom
UB7 "SN74LVC2G14DBVR" SOT95P280X145-6N_1 -70.54,-676.55 r90 bottom
UB8 "MCP6292-E/MS" TSOP65P580X110-8N 888.52,-790.72 r180 bottom
UB9 "ISO7810DWR" SOIC127P1030X265-16N -187.01,-1053.86 r90 bottom
UB10 "TS431IYLT" SOT95P280X145-5N 836.94,-963.52 r180 bottom
UB11 "LT3015EDD#TRPBF" 8-WDFN_EXPOSED_PAD 216.89,-1380.06 r90 bottom
UT1 "MGJ2D121505SC" MGJ2D121505SC 247.86,799.76 r90 top
UT2 "ADUM4146C" SOIC127P1032X265-16N -187.01,1053.55 r90 top
UT3 "AND_4_2x" D14 -95.45,464.94 r0 top
UT4 "SN74LVC1G32DCKR" SOT65P210X110-5N -305.01,-375.06 r0 top
UT5 "XOR2 2X" US8_2P40X2P10_ONS -10.01,-404.98 r270 top
UT6 "MGJ2D121505SC" MGJ2D121505SC 445.58,-794.53 r270 top
UT7 "ADUM4146C" SOIC127P1032X265-16N -187.01,-1053.86 r270 top
UT8 "LTC6992CS6-2#TRMPBF" SOT95P280X100-6N 886.94,-1113.52 r270 top

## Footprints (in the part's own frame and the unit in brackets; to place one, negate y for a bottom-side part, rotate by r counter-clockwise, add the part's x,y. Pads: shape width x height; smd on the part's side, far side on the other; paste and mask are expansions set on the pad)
8-WDFN_EXPOSED_PAD [mil]
  rect 25x12 smd mask+0: 1(-55.12,29.52) 2(-55.12,9.84) 3(-55.12,-9.84) 4(-55.12,-29.52) 5(55.12,-29.52) 6(55.12,-9.84) 7(55.12,9.84) 8(55.12,29.52)
  rect 70x105 smd mask+0: 9(0,0)
  silkscreen extent -41,68 -31,78, body extent -63,-61 63,61, height 32
C_1206 [mil] "C1206"
  rect 40x70 smd mask+0: 1(-60,0) 2(60,0)
  silkscreen extent -31,-31 31,31, body extent -63,-31 63,31, height 55
CAP_EEE1HA101UP [mm]
  rect 4x2 smd mask+0: 1(-3.55,0) 2(3.55,0)
  silkscreen extent -4.9,-4.15 4.15,4.15, body extent -4.85,-4.15 4.85,4.15, height 10.2
CAPC1608X90N [mm] "C0603"
  rect 0.95x1 smd mask+0: 1(-0.8,0) 2(0.8,0)
  silkscreen extent 0,-0.4 0,0.4, body extent -0.8,-0.4 0.8,0.4, height 0.86
CON_2X2_100MIL_TH [mil]
  round 60 hole 40 mask+4.02: 1(-50,50) 2(-50,-50) 3(50,50) 4(50,-50)
  silkscreen extent -100,-100 100,100, body extent -101,-111 99,109, height 636
"CON_2x2_100mil_TH - NEW" [mil]
  round 60 hole 40 mask+4.02: 1(-50,50) 2(-50,-50) 3(50,50) 4(50,-50)
  silkscreen extent -100,-100 100,100, body extent -101,-111 99,109, height 636
CONN16_3020-16-0300-00_CNC [mm]
  rect 1x4.15 smd paste+0 mask+0: 1(-8.89,-3.575) 2(-8.89,3.575) 3(-6.35,-3.575) 4(-6.35,3.575) 5(-3.81,-3.575) 6(-3.81,3.575) 7(-1.27,-3.575) 8(-1.27,3.575) 9(1.27,-3.575) 10(1.27,3.575) 11(3.81,-3.575) 12(3.81,3.575) 13(6.35,-3.575) 14(6.35,3.575) 15(8.89,-3.575) 16(8.89,3.575)
  silkscreen extent -12.66,-6.6 12.54,4.6, body extent -11.79,-3.4 11.84,3.45, height 0.25
D14 [mil] "SOP14"
  rect 78x22 smd mask+0: 1(-97,150) 2(-97,100) 3(-97,50) 4(-97,0) 5(-97,-50) 6(-97,-100) 7(-97,-150) 8(97,-150) 9(97,-100) 10(97,-50) 11(97,0) 12(97,50) 13(97,100) 14(97,150)
  silkscreen extent -115,-177 84,205, body extent -122,-172 122,172, height 69
D_0805 [mil] "D0805"
  rect 35x60 smd mask+0: 1(-35,0) 2(35,0)
  silkscreen extent 13,-25 74,36, body extent -39,-25 39,25, height 39
DIOM4326X26N_DB4 [mm] "Molded Diode, 2-Leads, Body 4.28x2.58mm, IPC Medium Density"
  rect 1.4x1.64 smd: A(2.015,0) C(-2.015,0)
  silkscreen extent -2.69,-1.47 2,1.48, body extent -2.52,-1.45 2.52,1.45, height 2.65
DIOM4426X24N_DB3 [mm] "Molded Diode, 2-Leads, Body 4.38x2.59mm, IPC Medium Density"
  rect 1.78x2.16 smd: A(2.025,0) C(-2.025,0)
  silkscreen extent -2.82,-1.47 2,1.55, body extent -2.6,-1.46 2.6,1.46, height 2.44
DO-214AB-SMC [mil] "DO214AB"
  rect 100x130 smd mask+0: A(135,0) C(-135,0)
  silkscreen extent -63,-135 -39,115, body extent -158,-123 162,123, height 104
DPAK-3 [mil]
  rect 37x98 smd mask+0: 1(-90.16,-252.5) 3(90.16,-252.5)
  rect 267x273 smd mask+0: 2(0,0)
  silkscreen extent -108,-190 108,-150, body extent -133,-240 133,78, height 67
FUSE_SMD_SSQ2410 [mil] "F2410"
  rect 80x125 smd mask+0: 1(-100,0) 2(100,0)
  silkscreen extent -51,-53 52,53, body extent -120,-50 120,50, height 101
INDC1608X95N [mm] "L0603"
  rect 0.95x1 smd mask+0: 1(-0.8,0) 2(0.8,0)
  silkscreen extent 0,-0.4 0,0.4, body extent -0.8,-0.4 0.8,0.4, height 0.95
MGJ2D121505SC [mil] "Power Supply"
  rect 60x60 hole 45.28: 1(0,0)
  round 60 hole 45.28: 2(100,0) 5(400,0) 6(500,0) 7(600,0)
  silkscreen extent -106,-293 691,107, body extent -90,-288 678,98, height 493
MMCX-J-P-H-ST-TH1_PCB [mm]
  round 1.348 hole 0.84 mask+0.102: 1(0,0) 2(-1.27,1.27) 3(1.27,1.27) 4(-1.27,-1.27) 5(1.27,-1.27)
  silkscreen extent -1.78,-1.78 1.78,1.78
MOUNTING_HOLE [mil]
  round 0 hole 175 unplated: 1(0,0)
RES_2012_SAM [mm]
  rect 0.706x1.25 smd paste+0 mask+0: 1(-1.003,0) 2(1.003,0)
  silkscreen extent -0.51,-0.64 0.51,0.64, body extent -1,-0.63 1,0.63, height 0.65
RESC1608X06N [mm] "Chip Resistor, 2-Leads, Body 1.60x0.83mm, IPC Medium Density"
  rect 0.5x0.95 smd mask+0: 1(-0.65,0) 2(0.65,0)
  silkscreen extent -0.25,-0.4 0.25,0.4, body extent -0.75,-0.48 0.75,0.48, height 0.55
RESC1608X55N [mm] "R0603"
  rect 0.9x1 smd mask+0: 1(-0.8,-0.025) 2(0.8,0)
  silkscreen extent 0,-0.4 0,0.4
RESC2012X06N_510_698 [mm] "Chip Resistor, 2-Leads, Body 2.00x1.25mm, IPC Medium Density"
  rect 0.9x1.3 smd mask+0: 1(-1.05,0) 2(1.05,0)
  silkscreen extent -0.4,-0.6 0.4,0.6, body extent -1.1,-0.67 1.1,0.68, height 0.65
RESC6432X70N [mm] "R2512"
  rect 1.25x3.4 smd mask+0: 1(-3.05,0) 2(3.05,0)
  silkscreen extent 0,-1.35 0,1.38, body extent -3.15,-1.5 3.15,1.5, height 0.7
SOD123 [mm] "SOD123"
  rect 1x0.75 smd mask+0: A(1.8,0) C(-1.8,0)
  silkscreen extent -1.7,-0.8 1.35,0.97, body extent -1.72,-0.82 1.78,0.78, height 1.1
SOIC127P1030X265-16N [mm]
  rect 2.06x0.6 smd mask+0: 1(-4.64,4.445) 2(-4.64,3.175) 3(-4.64,1.905) 4(-4.64,0.635) 5(-4.64,-0.635) 6(-4.64,-1.905) 7(-4.64,-3.175) 8(-4.64,-4.445) 9(4.64,-4.445) 10(4.64,-3.175) 11(4.64,-1.905) 12(4.64,-0.635) 13(4.64,0.635) 14(4.64,1.905) 15(4.64,3.175) 16(4.64,4.445)
  silkscreen extent -3.86,-5.15 3.75,5.77
SOIC127P1032X265-16N [mm]
  rect 2.05x0.59 smd mask+0: 1(-4.655,4.445) 2(-4.655,3.175) 3(-4.655,1.905) 4(-4.655,0.635) 5(-4.655,-0.635) 6(-4.655,-1.905) 7(-4.655,-3.175) 8(-4.655,-4.445) 9(4.655,-4.445) 10(4.655,-3.175) 11(4.655,-1.905) 12(4.655,-0.635) 13(4.655,0.635) 14(4.655,1.905) 15(4.655,3.175) 16(4.655,4.445)
  silkscreen extent -4.3,-5.15 3.75,6, body extent -5.16,-5.15 5.16,5.15, height 2.65
SON50P300X300X100-11N [mm]
  rect 0.86x0.26 smd mask+0: 1(-1.435,1) 2(-1.435,0.5) 3(-1.435,0) 4(-1.435,-0.5) 5(-1.435,-1) 6(1.435,-1) 7(1.435,-0.5) 8(1.435,0) 9(1.435,0.5) 10(1.435,1)
  rect 1.575x2.45 smd paste-2 mask+0: 11(0,0)
  silkscreen extent -1.8,-1.55 1.55,1.98
SOT65P210X110-5N [mm] "SOT23, 5-Leads, Body 2.00x2.10mm, Pitch 0.65mm, IPC Medium Density"
  rect 1x0.4 smd mask+0: 1(-1.1,0.65) 2(-1.1,0) 3(-1.1,-0.65) 4(1.1,-0.65) 5(1.1,0.65)
  silkscreen extent -1.22,-1.1 0.3,1.52, body extent -1.2,-1.07 1.2,1.08, height 1.1
SOT65P210X110-6N_UB4 [mm] "SOT23, 6-Leads, Body 2.00x2.10mm, Pitch 0.65mm, IPC Medium Density"
  rect 0.85x0.35 smd mask+0: 1(-1.1,0.65) 2(-1.1,0) 3(-1.1,-0.65) 4(1.1,-0.65) 5(1.1,0) 6(1.1,0.65)
  silkscreen extent -0.92,-1.14 0.61,1.23, body extent -0.7,-1.07 0.7,1.08, height 1.1
SOT95P280X100-6N [mm] "SOT23, 6-Leads, Body 2.90x2.80mm, Pitch 0.95mm, IPC Medium Density"
  rect 1.22x0.62 smd mask+0: 1(-1.31,0.95) 2(-1.31,0) 3(-1.31,-0.95) 4(1.31,-0.95) 5(1.31,0) 6(1.31,0.95)
  silkscreen extent -1.43,-1.45 0.64,1.94, body extent -1.4,-1.45 1.4,1.45, height 1
SOT95P280X145-5N [mm] "SOT23, 5-Leads, Body 2.90x2.80mm, Pitch 0.95mm, IPC Medium Density"
  rect 1.1x0.6 smd: 1(-1.3,0.95) 2(-1.3,0) 3(-1.3,-0.95) 4(1.3,-0.95) 5(1.3,0.95)
  silkscreen extent -1.43,-1.5 0.56,1.92, body extent -1.5,-1.5 1.5,1.5, height 1.45
SOT95P280X145-6N_1 [mm] "SOT23, 6-Leads, Body 2.90x2.80mm, Pitch 0.95mm, IPC Medium Density"
  rect 1.1x0.6 smd mask+0: 1(-1.3,0.95) 2(-1.3,0) 3(-1.3,-0.95) 4(1.3,-0.95) 5(1.3,0) 6(1.3,0.95)
  silkscreen extent -1.6,-1.5 0.5,1.9, body extent -1.5,-1.53 1.5,1.53, height 1.45
SOT_23_3 [mil] "SOT23_3"
  rect 31x35 smd mask+0: 1(37,39.5) 2(-37,39.5) 3(0,-39.5)
  silkscreen extent -65,-14 81,26, body extent -59,-47 59,47, height 39
SRF0905 [mil] "SRF0905"
  rect 75x50 smd mask+0: 1(-147,50) 2(-147,-50) 3(147,-50) 4(147,50)
  silkscreen extent -213,104 -211,106, body extent -181,-118 181,118, height 189
TSOP65P580X110-8N [mm] "TSOP, 8-Leads, Body 3.00x3.00mm, Pitch 0.65mm, IPC Medium Density"
  rect 1.45x0.45 smd mask+0: 1(-2.5,0.975) 2(-2.5,0.325) 3(-2.5,-0.325) 4(-2.5,-0.975) 5(2.5,-0.975) 6(2.5,-0.325) 7(2.5,0.325) 8(2.5,0.975)
  silkscreen extent -2.06,-1.5 1.4,1.65, body extent -2.93,-1.5 2.93,1.5, height 1.1
TSSOP_16 [mil] "TSSOP16"
  rect 65x13 smd mask+0: 1(-113,89.6) 2(-113,64) 3(-113,38.4) 4(-113,12.8) 5(-113,-12.8) 6(-113,-38.4) 7(-113,-64) 8(-113,-89.6) 9(113,-89.6) 10(113,-64) 11(113,-38.4) 12(113,-12.8) 13(113,12.8) 14(113,38.4) 15(113,64) 16(113,89.6)
  silkscreen extent -91,-100 80,124, body extent -126,-100 126,100, height 43
US8_2P40X2P10_ONS [mil]
  rect 31.5x10 smd paste+0 mask+0: 1(-61.25,29.53) 2(-61.25,9.84) 3(-61.25,-9.84) 4(-61.25,-29.53) 5(61.25,-29.53) 6(61.25,-9.84) 7(61.25,9.84) 8(61.25,29.53)
  silkscreen extent -50,-45 37,54, body extent -63,-39 63,39, height 35

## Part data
CB1 CB13 CB14 CB15 CB20 CB21 CB26 CB27 CB29 CB30 CB32 CB38 CT4 CT9 CT10 CT12 CT14 CT20 CT21 CT23: library part CAP_2.2uF, "CAP CER 2.2UF 50V X5R 0603", Manufacturer="Murata Electronics North America", Manufacturer PN=GRT188R61H225ME13D, Package Size="0603 (1608 Metric)", Rated Voltage=50V, Supplier Part Number 1=490-12333-1-ND, Temperature Coefficient=X5R, Tolerance=20%
CB2 CB3 CB4 CB5 CB6 CB8 CB19 CB28 CB33 CB34 CB35 CB36 CB37 CT1 CT3 CT24 CT25: library part CAP_10uF, "CAP CER 10UF 16V X7R 1206", Dielectric Type=Capacitors, Manufacturer="Murata Electronics North America", Manufacturer PN=GCM31CR71C106KA64L, Package Size="1206 (3216 Metric)", Rated Voltage=16V, Supplier Part Number 1=490-4793-1-ND, Temperature Coefficient=X7R, Tolerance=10%
CB7 CB17 CB25 CB31: library part CAP, "CAP CER 10000PF 25V 10% X7R 0603", Dielectric Type=Capacitors, Manufacturer="Samsung Electro-Mechanics America, Inc.", Manufacturer PN=CL10B103KA8NNNC, Package Size="0603 (1608 Metric)", Rated Voltage=25V, Supplier Part Number 1=1276-1132-2-ND, Temperature Coefficient=X7R, Tolerance=10%
CB9 CB10 CB11 CB12 CB16 CB18 CB22 CB23 CB24 CT5 CT6 CT7 CT8 CT13 CT15 CT16 CT17 CT18 CT19: library part CAP_Dup1, "CAP CER 56PF 50V C0G/NP0 0603", Dielectric Type=Capacitors, Manufacturer="Samsung Electro-Mechanics", Manufacturer PN=CL10C560JB8NNNC, Package Size="0603 (1608 Metric)", Temperature Coefficient="C0G, NP0", Tolerance=5%
CT2 CT26: library part CAP_Dup1, "CAP CER 56PF 50V C0G/NP0 0603", Dielectric Type=Capacitors, Manufacturer="Samsung Electro-Mechanics", Manufacturer PN=CL10C560JB8NNNC, Package Size="0603 (1608 Metric)", Supplier Part Number 1=187-CL10C560JB8NNNC, Temperature Coefficient="C0G, NP0", Tolerance=5%
CT11: library part CAP_100uF, "CAP ALUM 100UF 20% 50V SMD", Dielectric Type="Aluminum Electrolitic", Manufacturer="Panasonic Electronic Components", Manufacturer PN=EEE-1HA101UP, Package Size="Radial, Can - SMD", Supplier Part Number 1=667-EEE-1HA101UP, Tolerance=20%
CT22: library part CAP_1UF, "CAP CER 1UF 10V X7R 0603", Capacitance=1uF, Case Code (Imperial)=0603, Case Code (Metric)=1608, Dielectric=X7R, Manufacturer=Samsung, Manufacturer Part Number=CL10B105KP8NNNC, Max Operating Temperature=125°C, Min Operating Temperature=-55°C, Package Quantity=1, Supplier Part Number 1=1276-1946-1-ND, Tolerance=10%, Voltage Rating=10V
DB1 DB2 DB5: "DIODE GEN PURP 1KV 3A SMC", Average Rectified Current=1A, Case/Package=SMC, Manufacturer=Diodes, Max Forward Surge Current (Ifsm)=30A, Max Operating Temperature=150°C, Max Repetitive Reverse Voltage (Vrrm)=1kV, Min Operating Temperature=-55°C, Supplier Part Number 1=US3M-13DICT-ND
DB3: library part DIODE_ZENER_3, "DIODE ZENER 20V 1.5W DO214AC", Case/Package=DO-214AC, Manufacturer="Micro Commercial Co", Max Operating Temperature=150°C, Max Power Dissipation=1.5W, Max Reverse Leakage Current=500nA, Min Operating Temperature=-65°C, Package Quantity=1, Package Size=SOD-123, Supplier Part Number 1=SMAJ5932BTPMSCT-ND, Test Current=18.7mA, Tolerance=5%, Voltage Rating (DC)=20V
DB4: library part DIODE_SCHOTTKY_13, "DIODE SCHOTTKY 150V 2A SMA", Average Rectified Current=2A, Case/Package=SMA, Forward Voltage=890mV, Manufacturer=STMicroelectronics, Max Forward Surge Current (Ifsm)=75A, Max Operating Temperature=175°C, Max Repetitive Reverse Voltage (Vrrm)=150V, Max Reverse Current=1.5uA, Min Operating Temperature=-65°C, Package Quantity=1, Package Size="DO-214AC, SMA", Rated Voltage="820mV @ 2A", Supplier Part Number 1=497-2467-1-ND
DT1 DT7: library part DIODE_SCHOTTKY_11, "DIODE SCHOTTKY 30V 200MA SOD123", Manufacturer="Micro Commercial Co", Package Size=SOD-123, Rated Voltage="30 V", Supplier Part Number 1=833-BAT42W-TP
DT2: library part US3M-13_TOP, "DIODE GEN PURP 1KV 3A SMC", Average Rectified Current=1A, Case/Package=SMC, Max Forward Surge Current (Ifsm)=30A, Max Operating Temperature=150°C, Max Repetitive Reverse Voltage (Vrrm)=1kV, Min Operating Temperature=-55°C, Supplier Part Number 1=US3M-13DICT-ND
DT3 DT5: library part LED, "LED GREEN DIFFUSED 0805 SMD", Manufacturer="OSRAM Opto Semiconductors Inc.", Package Size="0805 (2012 Metric)", Rated Voltage=2.2V, Supplier Part Number 1=1152237
DT4 DT6: library part LED_1, "LED RED DIFFUSED 0805 SMD", Manufacturer="OSRAM Opto Semiconductors Inc.", Package Size="0805 (2012 Metric)", Rated Voltage="1.8V @ 20mA", Supplier Part Number 1=475-1415-1-ND
FT1 FT2: library part FUSE, "FUSE BOARD MNT 750MA 125VAC/VDC", Manufacturer="Bel Fuse Inc.", Manufacturer PN="SSQ 750", Package Size="0.240\" L x 0.100\" W x 0.100\" H (6.10mm x 2.54mm x 2.54mm)"
JT1 JT7: "CONN MMCX JACK STR 50 OHM PCB", Frequency=6Hz, Manufacturer=Samtec, Max Operating Temperature=90°C, Min Operating Temperature=-40°C, Operating Frequency="0 to 6Hz"
JT2 JT5: library part CON_2x2_100mil, "Conn Elevated Socket SKT 4 POS 2.54mm Solder ST Thru-Hole", Manufacturer=Samtec, Supplier Part Number 1=ESQ-102-33-L-D-ND
JT3 JT6: library part CON_2x2_100mil_NEW, "Conn Elevated Socket SKT 4 POS 2.54mm Solder ST Thru-Hole", Manufacturer=Samtec, Supplier Part Number 1=ESQ-102-33-L-D-ND
JT4: library part CON16A_Corrected, "CONN HEADER SMD 16POS 2.54MM", Contact Voltage=-, Manufacturer="Sullins Connector Solutions", Manufacturer PN=SBH11-NBPC-D08-SM-BK
LB1 LB2 LB3 LB4: library part INDUCTOR, "FIXED IND 1UH 600MA 150 MOHM SMD", Manufacturer="TDK Corporation", Manufacturer PN=MLZ1608A1R0WT000, Package Size="0603 (1608 Metric)", Supplier Part Number 1=445-6384-1-ND, Tolerance=20%
LT1 LT2: library part "CM choke - LPD3015_2", "INDUCTOR COMMON MODE 10UH 1.6A", Manufacturer="Bourns Inc.", Manufacturer PN=SRF0905-100Y, Package Size="Horizontal, 4 PC Pad", Supplier Part Number 1=SRF0905-100YCT-ND
RB1 RB22: library part RES_5, "RES SMD 0 OHM JUMPER 1/8W 0805", Manufacturer="Samsung Electro-Mechanics", Manufacturer PN=RC2012J000CS, Package Size="0805 (2012 Metric)", Rated Power="0.125W, 1/8W", Temperature Coefficient=-, Tolerance=Jumper
RB2 RB19: library part RES_2_BOT, "RES SMD 2.2K OHM 1% 1/10W 0603", Manufacturer=Yageo, Manufacturer PN=RC0603FR-072K2L, Package Size="0603 (1608 Metric)", Rated Power="0.1W, 1/10W", Temperature Coefficient=100ppm/C, Tolerance=1%
RB3 RB4 RB6 RB9 RB14 RB20 RB21 RT10 RT16 RT19 RT24 RT25 RT26 RT27 RT31 RT35 RT37: library part RES, "RES SMD 10K OHM 1% 1/10W 0603", Manufacturer="Panasonic Electronic Components", Manufacturer PN=ERJ-3EKF1002V, Package Size="0603 (1608 Metric)", Rated Power="0.1W, 1/10W", Temperature Coefficient=100ppm/C, Tolerance=1%
RB5 RB7 RB8 RB10 RB11 RB12 RB13 RT7 RT8 RT9 RT11 RT12 RT13 RT14 RT20 RT22 RT23 RT29 RT30: library part RES_1, "RES SMD 120 OHM 1% 1/10W 0603", Manufacturer=Yageo, Manufacturer PN=RC0603FR-07120RL, Package Size="0603 (1608 Metric)", Rated Power="0.1W, 1/10W", Supplier Part Number 1=311-120HRCT-ND, Temperature Coefficient=100ppm/C, Tolerance=1%
RB15: library part RES, "RES SMD 10K OHM 1% 1/10W 0603", Manufacturer="Panasonic Electronic Components", Package Size="0603 (1608 Metric)", Rated Power="0.1W, 1/10W", Temperature Coefficient=100ppm/C, Tolerance=1%
RB16: library part RES_9_BOTTOM, "RES 249K OHM 1% 1/10W 0603", Case Code (Imperial)=0603, Case Code (Metric)=1608, Manufacturer=Yageo, Manufacturer Part Number=RC0603FR-07249KL, Max Operating Temperature=155°C, Max Power Dissipation=100mW, Min Operating Temperature=-55°C, Package Quantity=1, Resistance=249kR, Resistor Type="Thick Film", Supplier Part Number 1=311-249KHRCT-ND, Temperature Coefficient=100ppm/°C, Tolerance=1%, Voltage Rating=50V
RB17: library part RES_10B, "RES SMD 100K OHM 1% 1/10W 0603", Case Code (Imperial)=0603, Case Code (Metric)=1608, Manufacturer="TE Connectivity", Manufacturer Part Number=CRG0603F100K, Max Operating Temperature=125°C, Min Operating Temperature=-55°C, Number of Resistors=1, Package Quantity=5000, Power Rating=100mW, Resistance=100kR, Resistor Type="Thick Film", Supplier Part Number 1=A106046CT-ND, Temperature Coefficient=100ppm/°C, Tolerance=1%, Voltage Rating=50V
RB18: library part RES_11, "RES 4.99K OHM 1% 1/10W 0603", Case Code (Imperial)=0603, Case Code (Metric)=1608, Manufacturer=Yageo, Manufacturer Part Number=RC0603FR-074K99L, Max Operating Temperature=155°C, Max Power Dissipation=100mW, Min Operating Temperature=-55°C, Package Quantity=1, Resistance=4.99kR, Resistance Tolerance=1%, Resistor Type="Thick Film", Supplier Part Number 1=311-4.99KHRCT-ND, Temperature Coefficient=100ppm/°C, Voltage Rating=75V, Voltage Rating (DC)=50V
RT1 RT40: library part RES_7, "RES SMD 510 OHM 1% 0.4W 0805", Case/Package=0805, Manufacturer="Vishay Dale", Manufacturer Part Number=RCS0805510RFKEA, Max Operating Temperature=155°C, Max Power Dissipation=400mW, Min Operating Temperature=-55°C, Package Quantity=5000, Resistance=510R, Resistor Type="Thick Film", Supplier Part Number 1=541-RCS0805510RFKEACT-ND, Temperature Coefficient=100ppm/°C, Tolerance=1%
RT2 RT39: library part RES_8_887, "RES 887 OHM 1% 1/8W 0805", Case Code (Imperial)=0805, Case Code (Metric)=2012, Manufacturer="Stackpole Electronics", Manufacturer Part Number=RMCF0805FT887R, Max Operating Temperature=155°C, Max Power Dissipation=125mW, Min Operating Temperature=-55°C, Resistance=887R, Resistor Type="Thick Film", Supplier Part Number 1=738-RMCF0805FT887RCT-ND, Temperature Coefficient=100ppm/°C, Tolerance=1%
RT3 RT42: library part RES_6, "RES 1K OHM 1% 1/8W 0603", Case Code (Imperial)=0603, Case Code (Metric)=1608, Manufacturer="Stackpole Electronics", Manufacturer Part Number=RNCP0603FTD1K00, Max Operating Temperature=155°C, Max Power Dissipation=125mW, Min Operating Temperature=-55°C, Resistance=1kR, Resistor Type="Thin Film", Temperature Coefficient=100ppm/°C, Tolerance=1%
RT4 RT15 RT17 RT18 RT21 RT28 RT41: library part RES_3, "RES SMD 330 OHM 5% 1/10W 0603", Manufacturer=Yageo, Manufacturer PN=RC0603JR-07330RL, Package Size="0603 (1608 Metric)", Rated Power="0.1W, 1/10W", Temperature Coefficient=100ppm/C, Tolerance=5%
RT5 RT6 RT33 RT34: library part RES_4, "RES SMD 1 OHM 1% 1.5W 2512", Manufacturer="Vishay Dale", Manufacturer PN=CRCW25121R00FKEGHP, Package Size="2512 (6432 Metric)", Rated Power=1.5W, Supplier Part Number 1=65AC3493, Temperature Coefficient=100ppm/C, Tolerance=1%
RT32: library part RES_12, "RES 0 OHM JUMPER 0603", Case/Package=Molded, Manufacturer="Vishay Dale", Manufacturer Part Number=WSL060300000ZEA9, Max Operating Temperature=170°C, Min Operating Temperature=-65°C, Resistance=0mR, Resistor Type="Metal Strip", Supplier Part Number 1=541-3927-1-ND
RT36: library part RES_9_TOP, "RES 249K OHM 1% 1/10W 0603", Case Code (Imperial)=0603, Case Code (Metric)=1608, Manufacturer=Yageo, Manufacturer Part Number=RC0603FR-07249KL, Max Operating Temperature=155°C, Max Power Dissipation=100mW, Min Operating Temperature=-55°C, Package Quantity=1, Resistance=249kR, Resistor Type="Thick Film", Supplier Part Number 1=311-249KHRCT-ND, Temperature Coefficient=100ppm/°C, Tolerance=1%, Voltage Rating=50V
RT38: library part RES_10, "RES SMD 100K OHM 1% 1/10W 0603", Case Code (Imperial)=0603, Case Code (Metric)=1608, Manufacturer="TE Connectivity", Manufacturer Part Number=CRG0603F100K, Max Operating Temperature=125°C, Min Operating Temperature=-55°C, Number of Resistors=1, Package Quantity=5000, Power Rating=100mW, Resistance=100kR, Resistor Type="Thick Film", Supplier Part Number 1=A106046CT-ND, Temperature Coefficient=100ppm/°C, Tolerance=1%, Voltage Rating=50V
UB1 UB11: library part LT3015, "IC REG LINEAR NEG ADJ 1.5A 8DFN", Manufacturer="Linear Technology/Analog Devices", Package Size="8-WFDFN Exposed Pad", Supplier Part Number 1=584-LT3015EDD#TRPBF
